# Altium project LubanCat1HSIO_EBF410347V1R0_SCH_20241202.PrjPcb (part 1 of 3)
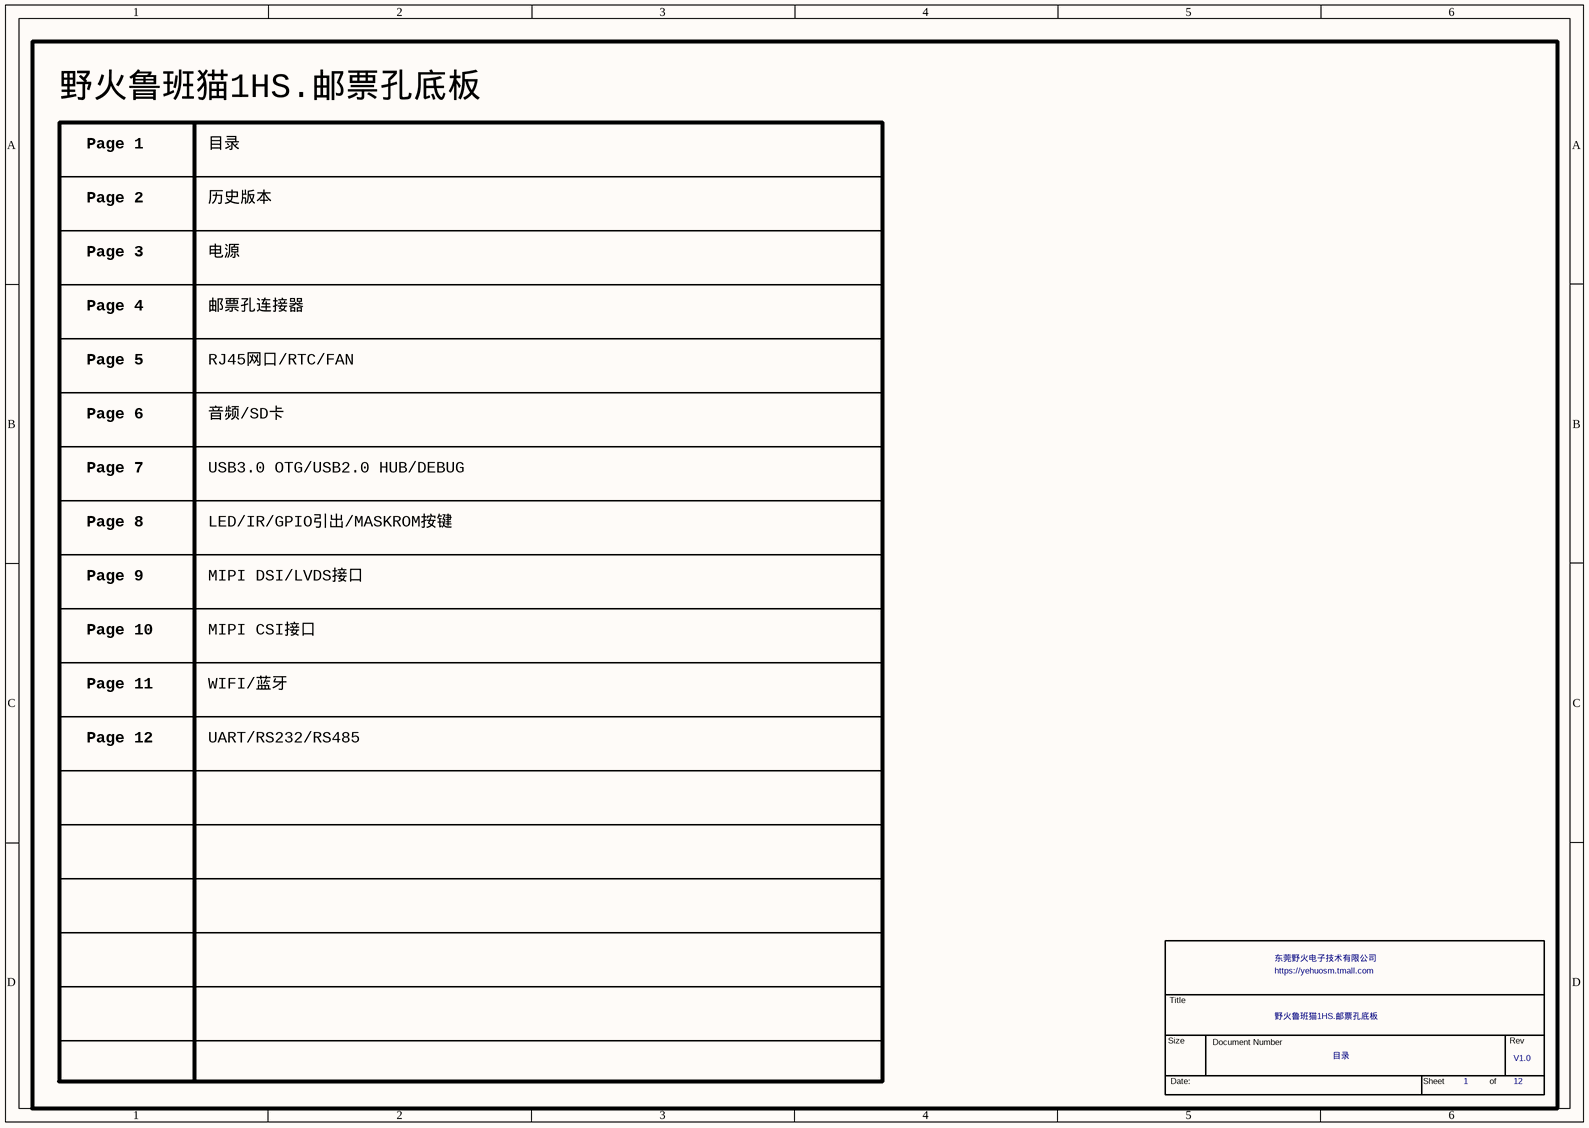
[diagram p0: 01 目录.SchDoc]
12 sheets, 578 parts. Net scope: global (net labels, ports and power ports of the same name join across sheets).
Sheets:
  01 目录.SchDoc
  02 历史版本.SchDoc
  03 电源.SchDoc
  04 邮票孔连接器.SchDoc
  05 RJ45网口_RTC_FAN.SchDoc
  06 音频_SD卡.SchDoc
  07 USB3.SchDoc
  08 LED_IR_GPIO引出_MASKRO.SchDoc
  09 MIPI DSI_LVDS接口.SchDoc
  10 MIPI CSI接口.SchDoc
  11 WIFI_蓝牙.SchDoc
  12 UART_RS232_RS485.SchDoc

## Sheet 01 目录.SchDoc
size 297 x 209 mm

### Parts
(Parts that share a designator on the sheet are numbered #1, #2 ... from top to bottom, then left to right.)
*#1  Page Count: 12  Page Number: 1  OrgName: 东莞野火电子技术有限公司  Title: 野火鲁班猫1HS.邮票孔底板  RevCode: V1.0  Doc: 目录  (hidden comment: TitleBlock_YHSCH)  (graphical)

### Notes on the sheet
- 野火鲁班猫1HS.邮票孔底板
- Page 1
- Page 2
- 目录
- 历史版本
- Page 3
- 电源
- Page 4
- 邮票孔连接器
- Page 5
- RJ45网口/RTC/FAN
- Page 6
- Page 7
- 音频/SD卡
- USB3.0 OTG/USB2.0 HUB/DEBUG
- Page 8
- LED/IR/GPIO引出/MASKROM按键
- Page 9
- MIPI DSI/LVDS接口
- Page 10
- MIPI CSI接口
- Page 11
- Page 12
- UART/RS232/RS485
- WIFI/蓝牙

## Sheet 02 历史版本.SchDoc
size 297 x 209 mm
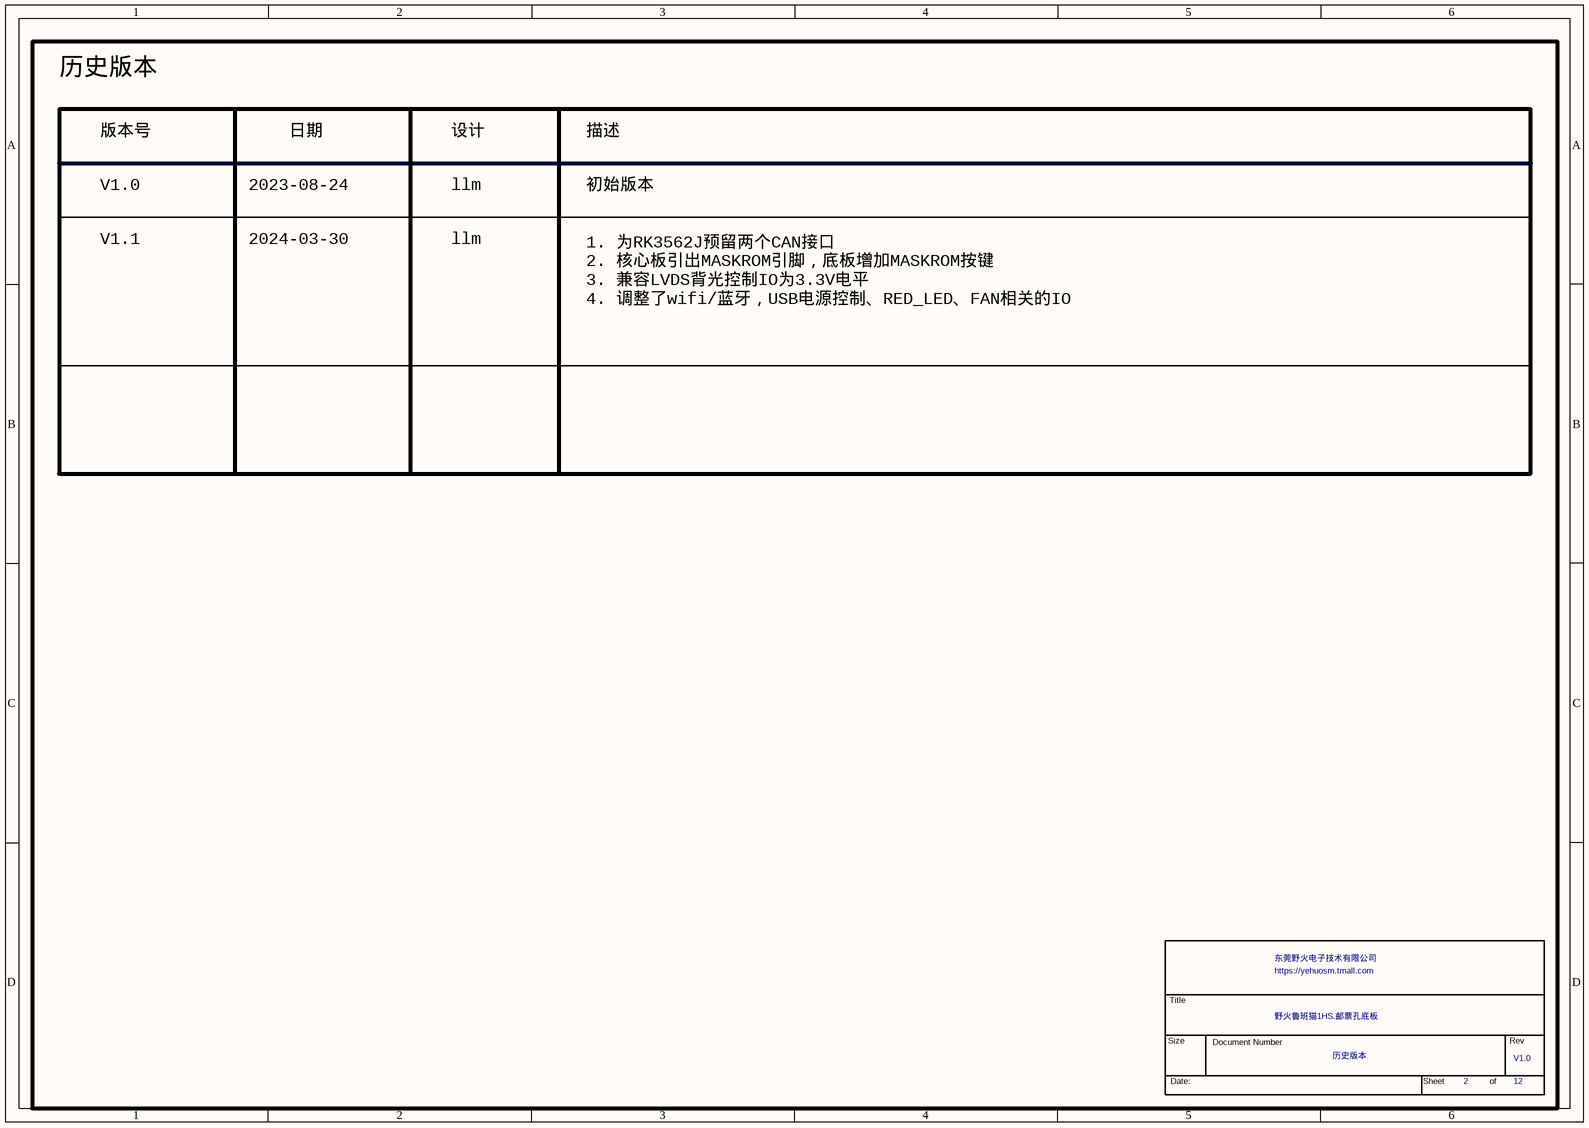
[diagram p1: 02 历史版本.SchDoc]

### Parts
(Parts that share a designator on the sheet are numbered #1, #2 ... from top to bottom, then left to right.)
*#2  Page Count: 12  Page Number: 2  OrgName: 东莞野火电子技术有限公司  Title: 野火鲁班猫1HS.邮票孔底板  RevCode: V1.0  Doc: 历史版本  (hidden comment: TitleBlock_YHSCH)  (graphical)

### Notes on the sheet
- 历史版本
- 版本号
- 日期
- 设计
- 描述
- V1.0
- 2023-08-24
- llm
- 初始版本
- V1.1
- 2024-03-30
- 1. 为RK3562J预留两个CAN接口
  2. 核心板引出MASKROM引脚，底板增加MASKROM按键
  3. 兼容LVDS背光控制IO为3.3V电平
  4. 调整了wifi/蓝牙，USB电源控制、RED_LED、FAN相关的IO

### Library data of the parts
*#2 = TitleBlock_YHSCH: Cage Code: 1

## Sheet 03 电源.SchDoc
size 297 x 209 mm
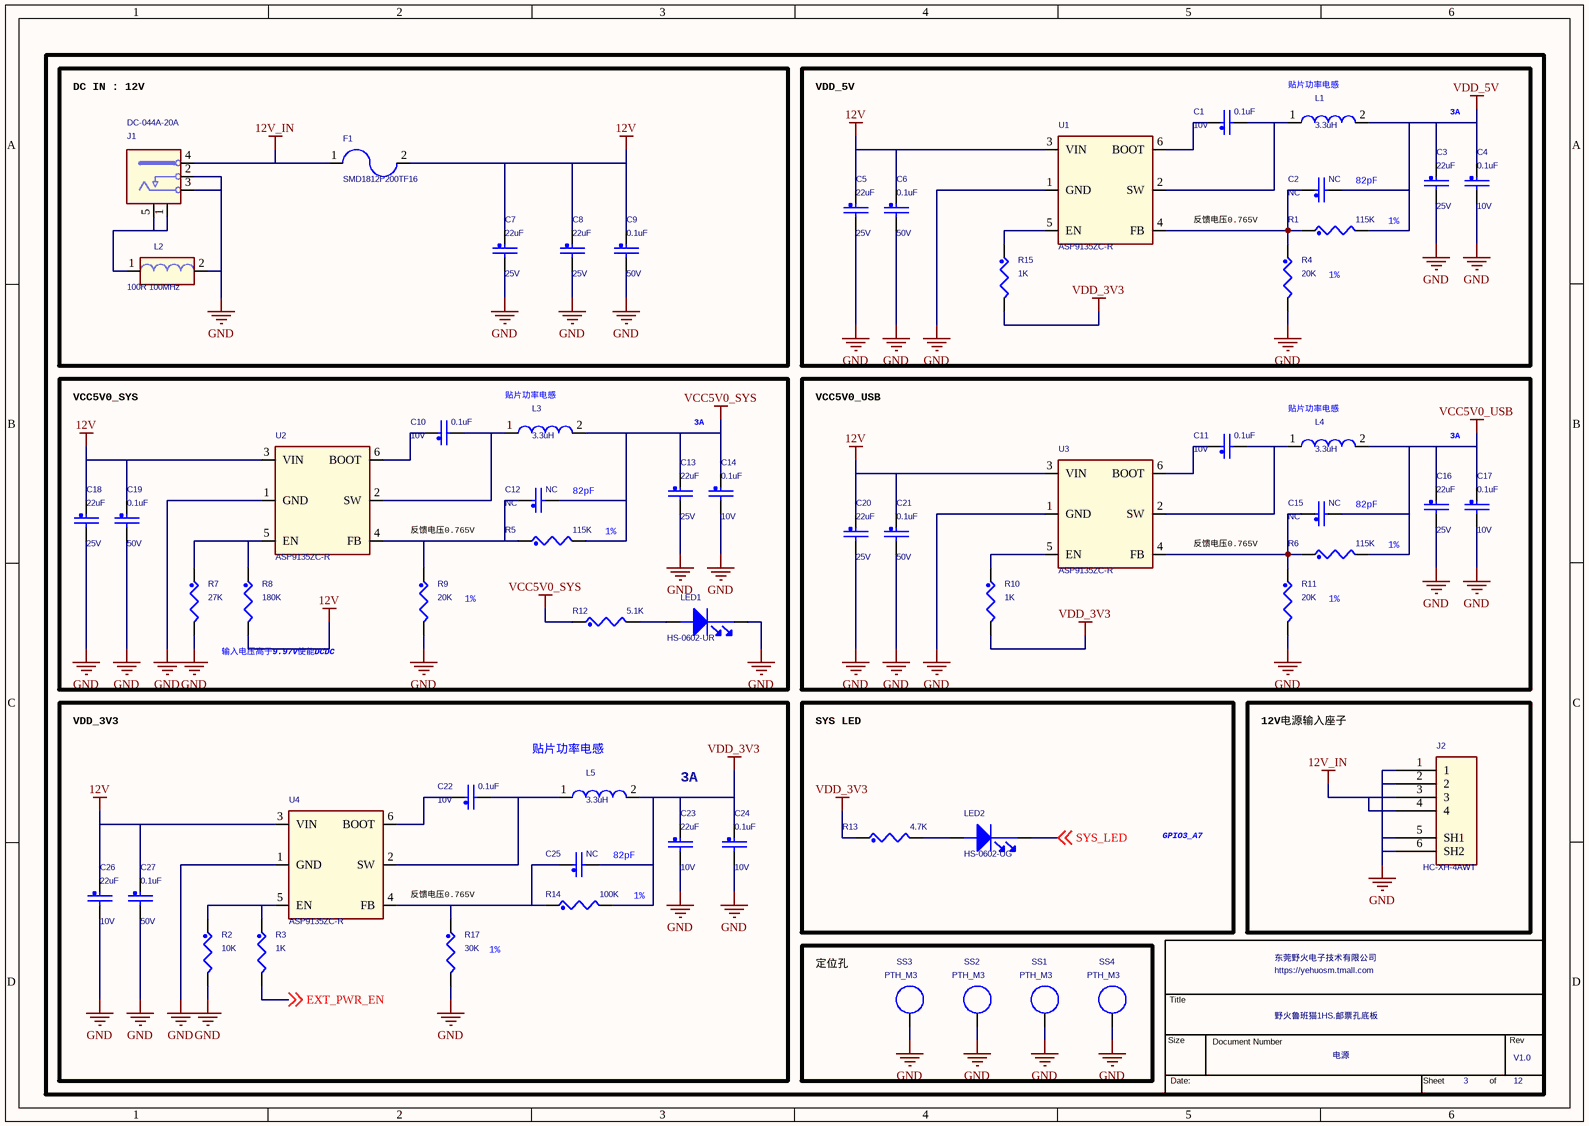
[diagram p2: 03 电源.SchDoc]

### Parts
(Parts that share a designator on the sheet are numbered #1, #2 ... from top to bottom, then left to right.)
*#3  Page Count: 12  Page Number: 3  OrgName: 东莞野火电子技术有限公司  Title: 野火鲁班猫1HS.邮票孔底板  RevCode: V1.0  Doc: 电源  (hidden comment: TitleBlock_YHSCH)  (graphical)
C1  0.1uF  Voltage: 10V  [C0402]
C2  NC  [C0402]
C3  22uF  Voltage: 25V  [C0805]
C4  0.1uF  Voltage: 10V  [C0402]
C5  22uF  Voltage: 25V  [C0805]
C6  0.1uF  Voltage: 50V  [C0402]
C7  22uF  Voltage: 25V  [C0805]
C8  22uF  Voltage: 25V  [C0805]
C9  0.1uF  Voltage: 50V  [C0402]
C10  0.1uF  Voltage: 10V  [C0402]
C11  0.1uF  Voltage: 10V  [C0402]
C12  NC  [C0402]
C13  22uF  Voltage: 25V  [C0805]
C14  0.1uF  Voltage: 10V  [C0402]
C15  NC  [C0402]
C16  22uF  Voltage: 25V  [C0805]
C17  0.1uF  Voltage: 10V  [C0402]
C18  22uF  Voltage: 25V  [C0805]
C19  0.1uF  Voltage: 50V  [C0402]
C20  22uF  Voltage: 25V  [C0805]
C21  0.1uF  Voltage: 50V  [C0402]
C22  0.1uF  Voltage: 10V  [C0402]
C23  22uF  Voltage: 10V  [C0603]
C24  0.1uF  Voltage: 10V  [C0402]
C25  NC  [C0402]
C26  22uF  Voltage: 10V  [C0603]
C27  0.1uF  Voltage: 50V  [C0402]
F1  SMD1812P200TF16  [F1812]
J1  DC-044A-20A  [dc_in_th_3p_10r1x11r6]
J2  HC-XH-4AWT  [HC-XH-4AWT]
L1  3.3uH  [l4520]
L2  100R 100MHz  [L0603]
L3  3.3uH  [l4520]
L4  3.3uH  [l4520]
L5  3.3uH  [l4520]
LED1  HS-0602-UR  [led_hs_0602_ur]
LED2  HS-0602-UG  [led_hs_0602_ur]
R1  115K  [R0402]
R2  10K  [R0402]
R3  1K  [R0402]
R4  20K  [R0402]
R5  115K  [R0402]
R6  115K  [R0402]
R7  27K  [R0402]
R8  180K  [R0402]
R9  20K  [R0402]
R10  1K  [R0402]
R11  20K  [R0402]
R12  5.1K  [R0402]
R13  4.7K  [R0402]
R14  100K  [R0402]
R15  1K  [R0402]
R17  30K  [R0402]
SS1  PTH_M3  [PTH_M3]
SS2  PTH_M3  [PTH_M3]
SS3  PTH_M3  [PTH_M3]
SS4  PTH_M3  [PTH_M3]
U1  ASP9135ZC-R  [SOT23_6]
U2  ASP9135ZC-R  [SOT23_6]
U3  ASP9135ZC-R  [SOT23_6]
U4  ASP9135ZC-R  [SOT23_6]

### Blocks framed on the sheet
DC IN : 12V: C7-C9 F1 J1 L2
VDD_5V: C1-C6 L1 R1 R4 R15 U1
VCC5V0_SYS: C10 C12-C14 C18 C19 L3 LED1 R5 R7-R9 R12 U2
VCC5V0_USB: C11 C15-C17 C20 C21 L4 R6 R10 R11 U3
3A: C22-C27 L5 R2 R3 R14 R17 U4
SYS LED: LED2 R13
12V电源输入座子: J2
定位孔: SS1-SS4

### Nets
12V: C5.1 C6.1 C7.1 C8.1 C9.1 C18.1 C19.1 C20.1 C21.1 C26.1 C27.1 F1.2 R8.2 U1.3(VIN) U2.3(VIN) U3.3(VIN) U4.3(VIN)
12V_IN: F1.1 J1.4 J2.3 J2.4
GND: C3.2 C4.2 C5.2 C6.2 C7.2 C8.2 C9.2 C13.2 C14.2 C16.2 C17.2 C18.2 C19.2 C20.2 C21.2 C23.2 C24.2 C26.2 C27.2 J1.2 J1.3 J2.1 J2.2 J2.5(SH1) J2.6(SH2) L2.2 LED1.1(CATHODE) R2.2 R4.2 R7.2 R9.2 R11.2 R17.2 SS1.1(NC_1) SS2.1(NC_1) SS3.1(NC_1) SS4.1(NC_1) U1.1(GND) U2.1(GND) U3.1(GND) U4.1(GND)
VCC5V0_SYS: C12.2 C13.1 C14.1 L3.2 R5.2 R12.1
VCC5V0_USB: C15.2 C16.1 C17.1 L4.2 R6.2
VDD_3V3: C23.1 C24.1 C25.2 L5.2 R10.2 R13.1 R14.2 R15.2
VDD_5V: C2.2 C3.1 C4.1 L1.2 R1.2
EXT_PWR_EN: R3.2 ; off-sheet EXT_PWR_EN
SYS_LED: LED2.1(CATHODE) ; off-sheet SYS_LED
NetC1_1: C1.1 U1.6(BOOT)
NetC1_2: C1.2 L1.1 U1.2(SW)
NetC2_1: C2.1 R1.1 R4.1 U1.4(FB)
NetC10_1: C10.1 U2.6(BOOT)
NetC10_2: C10.2 L3.1 U2.2(SW)
NetC11_1: C11.1 U3.6(BOOT)
NetC11_2: C11.2 L4.1 U3.2(SW)
NetC12_1: C12.1 R5.1 R9.1 U2.4(FB)
NetC15_1: C15.1 R6.1 R11.1 U3.4(FB)
NetC22_1: C22.1 U4.6(BOOT)
NetC22_2: C22.2 L5.1 U4.2(SW)
NetC25_1: C25.1 R14.1 R17.1 U4.4(FB)
NetJ1_1: J1.1 J1.5 L2.1
NetLED1_2: LED1.2(ANODE) R12.2
NetLED2_2: LED2.2(ANODE) R13.2
NetR2_1: R2.1 R3.1 U4.5(EN)
NetR7_1: R7.1 R8.1 U2.5(EN)
NetR10_1: R10.1 U3.5(EN)
NetR15_1: R15.1 U1.5(EN)

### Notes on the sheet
- (near L1) 贴片功率电感
- 3A
- 82pF
- 反馈电压0.765V
- 1%
- (near L3) 贴片功率电感
- (near L4) 贴片功率电感
- (near R5) 1%
- (near R9) 1%
- 输入电压高于9.97V使能DCDC
- VDD_3V3
- (near L5) 贴片功率电感
- (near C25) 82pF
- GPIO3_A7
- (near R17) 1%

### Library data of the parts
*#3 = TitleBlock_YHSCH: Cage Code: 1
C1 C4 C10 C11 C14 C17 C22 C24 = CAP_NP: CLASS: DISCRETE; 备注: H743挑战者; 生命周期: 量产; 价格: 0.003175; 规格书: 风华电容.pdf; 类别: 贴片电容0402; 品牌: 风华; 条码: EBFCIS230603155031; 规格编号: 0402B104K100NT; 规格: 贴片电容0.1uF 10% 10V X7R 0402
C2 C25 = CAP_NP: CLASS: DISCRETE; 规格: 贴片电容NC 预留; 条码: EBF29060149; 类别: 贴片电容0402
C3 C7 C8 C13 C18 C20 = CAP_NP: CLASS: DISCRETE; 规格: 贴片电容22uF 20% 25V X5R 0805; 规格编号: 0805X226M250NT; 条码: EBF29060173; 品牌: 风华; 类别: 贴片电容0805; 规格书: 风华电容.pdf; 价格: 0.285631; 生命周期: 量产
C5 C16 = CAP_NP: CLASS: DISCRETE; 生命周期: 量产; 价格: 0.285631; 规格书: 风华电容.pdf; 类别: 贴片电容0805; 品牌: 风华; 条码: EBF29060173; 规格编号: 0805X226M250NT; 规格: 贴片电容22uF 20% 25V X5R 0805
C6 C9 C27 = CAP_NP: CLASS: DISCRETE; 规格: 贴片电容0.1uF 10% 50V X5R 0402; 规格编号: 0402X104K500NT; 条码: EBF29060118; 品牌: 风华; 类别: 贴片电容0402; 规格书: 风华电容.pdf; 价格: 0.029826; 生命周期: 量产
C12 C15 = CAP_NP: CLASS: DISCRETE; 类别: 贴片电容0402; 条码: EBF29060149; 规格: 贴片电容NC 预留
C19 C21 = CAP_NP: CLASS: DISCRETE; 生命周期: 量产; 价格: 0.029826; 规格书: 风华电容.pdf; 类别: 贴片电容0402; 品牌: 风华; 条码: EBF29060118; 规格编号: 0402X104K500NT; 规格: 贴片电容0.1uF 10% 50V X5R 0402
C23 = CAP_NP: CLASS: DISCRETE; 生命周期: 量产; 价格: 0.078818; 规格书: 三星电容.pdf; 类别: 贴片电容0603; 品牌: 三星; 条码: EBF29060163; 规格编号: CL10A226MP8NUNE; 规格: 贴片电容22uF 20% 10V X5R 0603
C26 = CAP_NP: CLASS: DISCRETE; 规格: 贴片电容22uF 20% 10V X5R 0603; 规格编号: CL10A226MP8NUNE; 条码: EBF29060163; 品牌: 三星; 类别: 贴片电容0603; 规格书: 三星电容.pdf; 价格: 0.078818; 生命周期: 量产
F1 = FUSE: 生命周期: 量产; 价格: 0.385618; 规格书: 瑞隆源-自恢复保险丝.pdf; 类别: 自恢复保险丝; 品牌: 瑞隆源; 条码: EBF29270006; 规格: 自恢复保险丝 最大电压46V 最大电流100A 保持电流2A 跳闸电流4A
J1 = DC-044A-20A: 生命周期: 量产; 规格书: DC插座_内径_2MM外径_5.9MM.pdf; 类别: DC电源座; 条码: EBF29040093; 规格编号: DC-044A-20A DC; 规格: DC-044A-20A DC插座
J2 = 1X4PIN_SH: 规格: 间距：2.54mm 插针结构：1x4P 排数：1 每排PIN数：4 公母：公型插针 安装方式：卧贴 额定电流：3A 工作温度范围：-25℃~+85℃; 条码: EBFCIS230215084107; 品牌: 华灿天禄; 类别: XH连接器; 规格书: 华灿天禄_HC-XH-4AWT.pdf; 价格: 0.431422; 生命周期: 量产
L1 = IND: CLASS: DISCRETE; 价格: 1.5992; 规格编号: TMPC0402HP-3R3MG-Z02; 规格: 贴片电感3.3uH ±20% 3A 直流电阻69mΩ; 条码: EBF29050040; 品牌: 台庆; 类别: 贴片电感0402; 规格书: 台庆-功率电感.pdf; 生命周期: 量产
L2 = BEAD: CLASS: DISCRETE; 生命周期: 量产; 价格: 0.021567; 规格书: 顺络-磁珠.pdf; 类别: 贴片磁珠0603; 品牌: 顺络; 条码: EBF29050038; 规格编号: UPZ1608E101-3R0TF; 规格: 磁珠100Ω @100MHz 额定电流3A 直流电阻30mΩ
L3 L5 = IND: CLASS: DISCRETE; 价格: 1.5992; 规格编号: TMPC0402HP-3R3MG-Z02; 生命周期: 量产; 规格书: 台庆-功率电感.pdf; 类别: 贴片电感0402; 品牌: 台庆; 条码: EBF29050040; 规格: 贴片电感3.3uH ±20% 3A 直流电阻69mΩ
L4 = IND: CLASS: DISCRETE; 生命周期: 量产; 规格书: 台庆-功率电感.pdf; 类别: 贴片电感0402; 品牌: 台庆; 条码: EBF29050040; 规格: 贴片电感3.3uH ±20% 3A 直流电阻69mΩ; 规格编号: TMPC0402HP-3R3MG-Z02; 价格: 1.5992
LED1 = LED: 规格: 侧贴0602LED 红色; 条码: EBF29140054; 品牌: 鸿之森; 类别: 侧贴发光LED; 规格书: HS-0602-UR.pdf; 生命周期: 量产
LED2 = LED: 规格: 正向电压(VF)：3.2V 工作电流：5mA 功率：80mW 绿色; 条码: EBF29140060; 品牌: 鸿之森; 类别: 侧贴发光LED; 规格书: HS-0602-UG.pdf; 价格: 0.068705; 生命周期: 量产
R1 = RES: CLASS: DISCRETE; 生命周期: 量产; 价格: 0.006087; 规格书: YAGEO国巨厚膜无铅电阻.pdf; 类别: 贴片电阻0402; 品牌: 国巨; 条码: EBF29070290; 规格编号: AC0402FR-07115KL; 规格: 贴片电阻115K 1% 1/16W 0402
R2 = RES: CLASS: DISCRETE; 规格: 贴片电阻10K 1% 1/16W 0402; 规格编号: 0402WGF1002TCE; 条码: EBF29070046; 品牌: 厚声; 类别: 贴片电阻0402; 规格书: 厚声-无铅厚膜电阻.pdf; 价格: 0.002773; 生命周期: 量产
R3 = RES: CLASS: DISCRETE; 生命周期: 量产; 规格书: 合科泰-RI系列电阻.pdf; 类别: 贴片电阻0402; 品牌: 合科泰; 条码: EBF29070050; 规格编号: RI0402L1001FT; 规格: 贴片电阻1K 1% 1/16W 0402
R4 = RES: CLASS: DISCRETE; 生命周期: 量产; 价格: 0.002473; 规格书: 厚声-无铅厚膜电阻.pdf; 类别: 贴片电阻0402; 品牌: 厚声; 条码: EBF29070223; 规格编号: 0402WGF2002TCE; 规格: 贴片电阻20K 1% 1/16W 0402
R5 R6 = RES: CLASS: DISCRETE; 规格: 贴片电阻115K 1% 1/16W 0402; 规格编号: AC0402FR-07115KL; 条码: EBF29070290; 品牌: 国巨; 类别: 贴片电阻0402; 规格书: YAGEO国巨厚膜无铅电阻.pdf; 价格: 0.006087; 生命周期: 量产
R7 = RES: CLASS: DISCRETE; 生命周期: 量产; 价格: 0.007054; 规格书: YAGEO国巨厚膜无铅电阻.pdf; 类别: 贴片电阻0402; 品牌: 国巨; 条码: EBF29070003; 规格编号: AC0402FR-0727KL; 规格: 贴片电阻27K 1% 1/16W 0402
R8 = RES: CLASS: DISCRETE; 生命周期: 量产; 价格: 0.006152; 规格书: 厚声-无铅厚膜电阻.pdf; 类别: 贴片电阻0402; 品牌: 厚声; 条码: EBF29070288; 规格编号: CQ02WGF1803TCE; 规格: 贴片电阻180K 1% 1/16W 0402
R9 R11 = RES: CLASS: DISCRETE; 规格: 贴片电阻20K 1% 1/16W 0402; 规格编号: 0402WGF2002TCE; 条码: EBF29070223; 品牌: 厚声; 类别: 贴片电阻0402; 规格书: 厚声-无铅厚膜电阻.pdf; 价格: 0.002473; 生命周期: 量产
R10 R15 = RES: CLASS: DISCRETE; 规格: 贴片电阻1K 1% 1/16W 0402; 规格编号: RI0402L1001FT; 条码: EBF29070050; 品牌: 合科泰; 类别: 贴片电阻0402; 规格书: 合科泰-RI系列电阻.pdf; 生命周期: 量产
R12 = RES: CLASS: DISCRETE; 生命周期: 量产; 类别: 贴片电阻0402; 品牌: VO; 条码: EBF29070258; 规格编号: 0402F5101BV1906130014; 规格: 贴片电阻5.1K 1% 1/16W 0402
R13 = RES: CLASS: DISCRETE; 规格: 贴片电阻4.7K 1% 1/16W 0402; 规格编号: RI0402L4701FT; 条码: EBF29070047; 品牌: 合科泰; 类别: 贴片电阻0402; 规格书: 合科泰-RI系列电阻.pdf; 生命周期: 量产
R14 = RES: CLASS: DISCRETE; 规格: 贴片电阻100K 1% 1/16W 0402; 规格编号: RI0402L1003FT; 条码: EBF29070054; 品牌: 合科泰; 类别: 贴片电阻0402; 规格书: 合科泰-RI系列电阻.pdf; 生命周期: 量产
R17 = RES: CLASS: DISCRETE; 规格: 贴片电阻30K 1% 1/16W 0402; 规格编号: RI0402L3002FT; 条码: EBF29070048; 品牌: 合科泰; 类别: 贴片电阻0402; 规格书: 合科泰-RI系列电阻.pdf; 生命周期: 量产
SS1-SS4 = SPACER: CLASS: IC; 生命周期: 量产; 类别: M3螺丝孔; 品牌: 野火; 条码: EBFCIS220926100224; 规格编号: M3螺丝孔_有铜
U1-U4 = TP6327GS6: 备注: RK3566金手指与BTB底板替换物料; 生命周期: 量产; 规格书: 安森德_ASP9135ZC-R.pdf; 类别: 电源管理-DCDC; 品牌: 安森德; 条码: EBFCIS240710113940; 规格: DC-DC电源芯片 可输出电流 3A 开关工作频率 600kHz 输出类型 ADJ 输入电压范围：4V-18V

## Sheet 04 邮票孔连接器.SchDoc
size 297 x 209 mm
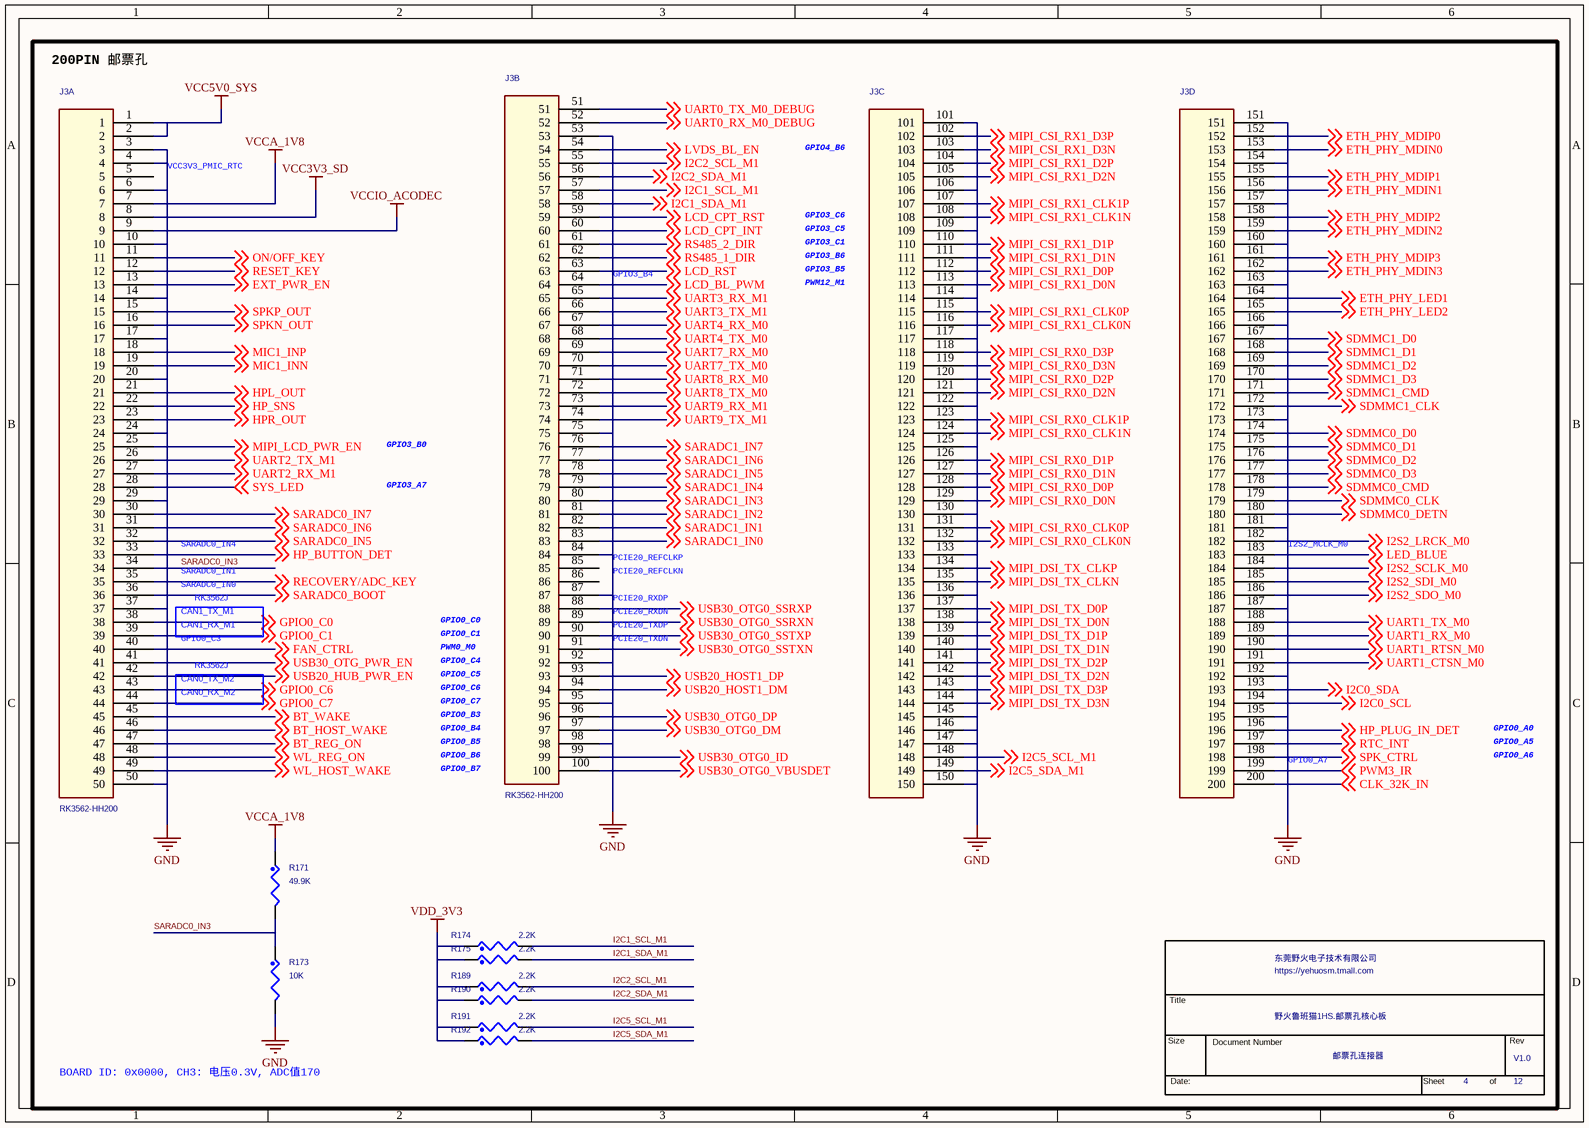
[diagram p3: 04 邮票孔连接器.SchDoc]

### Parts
(Parts that share a designator on the sheet are numbered #1, #2 ... from top to bottom, then left to right.)
*#4  Page Count: 12  Page Number: 4  OrgName: 东莞野火电子技术有限公司  Title: 野火鲁班猫1HS.邮票孔核心板  RevCode: V1.0  Doc: 邮票孔连接器  (hidden comment: TitleBlock_YHSCH)  (graphical)
J3  RK3562-HH200  [HH200-0R90-48R1X48R1-B]  (parts A,B,C,D of 4)
R171  49.9K  [R0402]
R173  10K  [R0402]
R174  2.2K  [R0402]
R175  2.2K  [R0402]
R189  2.2K  [R0402]
R190  2.2K  [R0402]
R191  2.2K  [R0402]
R192  2.2K  [R0402]

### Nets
GND: J3.3 J3.4 J3.6 J3.10 J3.14 J3.17 J3.20 J3.24 J3.29 J3.37 J3.50 J3.53 J3.75 J3.84 J3.87 J3.92 J3.95 J3.98 J3.101 J3.106 J3.109 J3.114 J3.117 J3.122 J3.125 J3.130 J3.133 J3.136 J3.145 J3.146 J3.147 J3.150 J3.151 J3.154 J3.157 J3.160 J3.163 J3.166 J3.173 J3.181 J3.187 J3.192 J3.195 R173.2
VCC3V3_SD: J3.8
VCC5V0_SYS: J3.1 J3.2
VCCA_1V8: J3.7 R171.1
VCCIO_ACODEC: J3.9
VDD_3V3: R174.1 R175.1 R189.1 R190.1 R191.1 R192.1
BT_HOST_WAKE: J3.46 ; off-sheet BT_HOST_WAKE
BT_REG_ON: J3.47 ; off-sheet BT_REG_ON
BT_WAKE: J3.45 ; off-sheet BT_WAKE
CLK_32K_IN: J3.200 ; off-sheet CLK_32K_IN
ETH_PHY_LED1: J3.164 ; off-sheet ETH_PHY_LED1
ETH_PHY_LED2: J3.165 ; off-sheet ETH_PHY_LED2
ETH_PHY_MDIN0: J3.153 ; off-sheet ETH_PHY_MDIN0
ETH_PHY_MDIN1: J3.156 ; off-sheet ETH_PHY_MDIN1
ETH_PHY_MDIN2: J3.159 ; off-sheet ETH_PHY_MDIN2
ETH_PHY_MDIN3: J3.162 ; off-sheet ETH_PHY_MDIN3
ETH_PHY_MDIP0: J3.152 ; off-sheet ETH_PHY_MDIP0
ETH_PHY_MDIP1: J3.155 ; off-sheet ETH_PHY_MDIP1
ETH_PHY_MDIP2: J3.158 ; off-sheet ETH_PHY_MDIP2
ETH_PHY_MDIP3: J3.161 ; off-sheet ETH_PHY_MDIP3
EXT_PWR_EN: J3.13 ; off-sheet EXT_PWR_EN
FAN_CTRL: J3.40 ; off-sheet FAN_CTRL
GPIO0_C0: J3.38 ; off-sheet GPIO0_C0
GPIO0_C1: J3.39 ; off-sheet GPIO0_C1
GPIO0_C6: J3.43 ; off-sheet GPIO0_C6
GPIO0_C7: J3.44 ; off-sheet GPIO0_C7
HP_BUTTON_DET: J3.33 ; off-sheet HP_BUTTON_DET
HP_PLUG_IN_DET: J3.196 ; off-sheet HP_PLUG_IN_DET
HP_SNS: J3.22 ; off-sheet HP_SNS
HPL_OUT: J3.21 ; off-sheet HPL_OUT
HPR_OUT: J3.23 ; off-sheet HPR_OUT
I2C0_SCL: J3.194 ; off-sheet I2C0_SCL
I2C0_SDA: J3.193 ; off-sheet I2C0_SDA
I2C1_SCL_M1: J3.57 R174.2 ; off-sheet I2C1_SCL_M1
I2C1_SDA_M1: J3.58 R175.2 ; off-sheet I2C1_SDA_M1
I2C2_SCL_M1: J3.55 R189.2 ; off-sheet I2C2_SCL_M1
I2C2_SDA_M1: J3.56 R190.2 ; off-sheet I2C2_SDA_M1
I2C5_SCL_M1: J3.148 R191.2 ; off-sheet I2C5_SCL_M1
I2C5_SDA_M1: J3.149 R192.2 ; off-sheet I2C5_SDA_M1
I2S2_LRCK_M0: J3.182 ; off-sheet I2S2_LRCK_M0
I2S2_SCLK_M0: J3.184 ; off-sheet I2S2_SCLK_M0
I2S2_SDI_M0: J3.185 ; off-sheet I2S2_SDI_M0
I2S2_SDO_M0: J3.186 ; off-sheet I2S2_SDO_M0
LCD_BL_PWM: J3.64 ; off-sheet LCD_BL_PWM
LCD_CPT_INT: J3.60 ; off-sheet LCD_CPT_INT
LCD_CPT_RST: J3.59 ; off-sheet LCD_CPT_RST
LCD_RST: J3.63 ; off-sheet LCD_RST
LED_BLUE: J3.183 ; off-sheet LED_BLUE
LVDS_BL_EN: J3.54 ; off-sheet LVDS_BL_EN
MIC1_INN: J3.19 ; off-sheet MIC1_INN
MIC1_INP: J3.18 ; off-sheet MIC1_INP
MIPI_CSI_RX0_CLK0N: J3.132 ; off-sheet MIPI_CSI_RX0_CLK0N
MIPI_CSI_RX0_CLK0P: J3.131 ; off-sheet MIPI_CSI_RX0_CLK0P
MIPI_CSI_RX0_CLK1N: J3.124 ; off-sheet MIPI_CSI_RX0_CLK1N
MIPI_CSI_RX0_CLK1P: J3.123 ; off-sheet MIPI_CSI_RX0_CLK1P
MIPI_CSI_RX0_D0N: J3.129 ; off-sheet MIPI_CSI_RX0_D0N
MIPI_CSI_RX0_D0P: J3.128 ; off-sheet MIPI_CSI_RX0_D0P
MIPI_CSI_RX0_D1N: J3.127 ; off-sheet MIPI_CSI_RX0_D1N
MIPI_CSI_RX0_D1P: J3.126 ; off-sheet MIPI_CSI_RX0_D1P
MIPI_CSI_RX0_D2N: J3.121 ; off-sheet MIPI_CSI_RX0_D2N
MIPI_CSI_RX0_D2P: J3.120 ; off-sheet MIPI_CSI_RX0_D2P
MIPI_CSI_RX0_D3N: J3.119 ; off-sheet MIPI_CSI_RX0_D3N
MIPI_CSI_RX0_D3P: J3.118 ; off-sheet MIPI_CSI_RX0_D3P
MIPI_CSI_RX1_CLK0N: J3.116 ; off-sheet MIPI_CSI_RX1_CLK0N
MIPI_CSI_RX1_CLK0P: J3.115 ; off-sheet MIPI_CSI_RX1_CLK0P
MIPI_CSI_RX1_CLK1N: J3.108 ; off-sheet MIPI_CSI_RX1_CLK1N
MIPI_CSI_RX1_CLK1P: J3.107 ; off-sheet MIPI_CSI_RX1_CLK1P
MIPI_CSI_RX1_D0N: J3.113 ; off-sheet MIPI_CSI_RX1_D0N
MIPI_CSI_RX1_D0P: J3.112 ; off-sheet MIPI_CSI_RX1_D0P
MIPI_CSI_RX1_D1N: J3.111 ; off-sheet MIPI_CSI_RX1_D1N
MIPI_CSI_RX1_D1P: J3.110 ; off-sheet MIPI_CSI_RX1_D1P
MIPI_CSI_RX1_D2N: J3.105 ; off-sheet MIPI_CSI_RX1_D2N
MIPI_CSI_RX1_D2P: J3.104 ; off-sheet MIPI_CSI_RX1_D2P
MIPI_CSI_RX1_D3N: J3.103 ; off-sheet MIPI_CSI_RX1_D3N
MIPI_CSI_RX1_D3P: J3.102 ; off-sheet MIPI_CSI_RX1_D3P
MIPI_DSI_TX_CLKN: J3.135 ; off-sheet MIPI_DSI_TX_CLKN
MIPI_DSI_TX_CLKP: J3.134 ; off-sheet MIPI_DSI_TX_CLKP
MIPI_DSI_TX_D0N: J3.138 ; off-sheet MIPI_DSI_TX_D0N
MIPI_DSI_TX_D0P: J3.137 ; off-sheet MIPI_DSI_TX_D0P
MIPI_DSI_TX_D1N: J3.140 ; off-sheet MIPI_DSI_TX_D1N
MIPI_DSI_TX_D1P: J3.139 ; off-sheet MIPI_DSI_TX_D1P
MIPI_DSI_TX_D2N: J3.142 ; off-sheet MIPI_DSI_TX_D2N
MIPI_DSI_TX_D2P: J3.141 ; off-sheet MIPI_DSI_TX_D2P
MIPI_DSI_TX_D3N: J3.144 ; off-sheet MIPI_DSI_TX_D3N
MIPI_DSI_TX_D3P: J3.143 ; off-sheet MIPI_DSI_TX_D3P
MIPI_LCD_PWR_EN: J3.25 ; off-sheet MIPI_LCD_PWR_EN
ON/OFF_KEY: J3.11 ; off-sheet ON/OFF_KEY
PWM3_IR: J3.199 ; off-sheet PWM3_IR
RECOVERY/ADC_KEY: J3.35 ; off-sheet RECOVERY/ADC_KEY
RESET_KEY: J3.12 ; off-sheet RESET_KEY
RS485_1_DIR: J3.62 ; off-sheet RS485_1_DIR
RS485_2_DIR: J3.61 ; off-sheet RS485_2_DIR
RTC_INT: J3.197 ; off-sheet RTC_INT
SARADC0_BOOT: J3.36 ; off-sheet SARADC0_BOOT
SARADC0_IN3: J3.34 R171.2 R173.1
SARADC0_IN5: J3.32 ; off-sheet SARADC0_IN5
SARADC0_IN6: J3.31 ; off-sheet SARADC0_IN6
SARADC0_IN7: J3.30 ; off-sheet SARADC0_IN7
SARADC1_IN0: J3.83 ; off-sheet SARADC1_IN0
SARADC1_IN1: J3.82 ; off-sheet SARADC1_IN1
SARADC1_IN2: J3.81 ; off-sheet SARADC1_IN2
SARADC1_IN3: J3.80 ; off-sheet SARADC1_IN3
SARADC1_IN4: J3.79 ; off-sheet SARADC1_IN4
SARADC1_IN5: J3.78 ; off-sheet SARADC1_IN5
SARADC1_IN6: J3.77 ; off-sheet SARADC1_IN6
SARADC1_IN7: J3.76 ; off-sheet SARADC1_IN7
SDMMC0_CLK: J3.179 ; off-sheet SDMMC0_CLK
SDMMC0_CMD: J3.178 ; off-sheet SDMMC0_CMD
SDMMC0_D0: J3.174 ; off-sheet SDMMC0_D0
SDMMC0_D1: J3.175 ; off-sheet SDMMC0_D1
SDMMC0_D2: J3.176 ; off-sheet SDMMC0_D2
SDMMC0_D3: J3.177 ; off-sheet SDMMC0_D3
SDMMC0_DETN: J3.180 ; off-sheet SDMMC0_DETN
SDMMC1_CLK: J3.172 ; off-sheet SDMMC1_CLK
SDMMC1_CMD: J3.171 ; off-sheet SDMMC1_CMD
SDMMC1_D0: J3.167 ; off-sheet SDMMC1_D0
SDMMC1_D1: J3.168 ; off-sheet SDMMC1_D1
SDMMC1_D2: J3.169 ; off-sheet SDMMC1_D2
SDMMC1_D3: J3.170 ; off-sheet SDMMC1_D3
SPK_CTRL: J3.198 ; off-sheet SPK_CTRL
SPKN_OUT: J3.16 ; off-sheet SPKN_OUT
SPKP_OUT: J3.15 ; off-sheet SPKP_OUT
SYS_LED: J3.28 ; off-sheet SYS_LED
UART0_RX_M0_DEBUG: J3.52 ; off-sheet UART0_RX_M0_DEBUG
UART0_TX_M0_DEBUG: J3.51 ; off-sheet UART0_TX_M0_DEBUG
UART1_CTSN_M0: J3.191 ; off-sheet UART1_CTSN_M0
UART1_RTSN_M0: J3.190 ; off-sheet UART1_RTSN_M0
UART1_RX_M0: J3.189 ; off-sheet UART1_RX_M0
UART1_TX_M0: J3.188 ; off-sheet UART1_TX_M0
UART2_RX_M1: J3.27 ; off-sheet UART2_RX_M1
UART2_TX_M1: J3.26 ; off-sheet UART2_TX_M1
UART3_RX_M1: J3.65 ; off-sheet UART3_RX_M1
UART3_TX_M1: J3.66 ; off-sheet UART3_TX_M1
UART4_RX_M0: J3.67 ; off-sheet UART4_RX_M0
UART4_TX_M0: J3.68 ; off-sheet UART4_TX_M0
UART7_RX_M0: J3.69 ; off-sheet UART7_RX_M0
UART7_TX_M0: J3.70 ; off-sheet UART7_TX_M0
UART8_RX_M0: J3.71 ; off-sheet UART8_RX_M0
UART8_TX_M0: J3.72 ; off-sheet UART8_TX_M0
UART9_RX_M1: J3.73 ; off-sheet UART9_RX_M1
UART9_TX_M1: J3.74 ; off-sheet UART9_TX_M1
USB20_HOST1_DM: J3.94 ; off-sheet USB20_HOST1_DM
USB20_HOST1_DP: J3.93 ; off-sheet USB20_HOST1_DP
USB20_HUB_PWR_EN: J3.42 ; off-sheet USB20_HUB_PWR_EN
USB30_OTG0_DM: J3.97 ; off-sheet USB30_OTG0_DM
USB30_OTG0_DP: J3.96 ; off-sheet USB30_OTG0_DP
USB30_OTG0_ID: J3.99 ; off-sheet USB30_OTG0_ID
USB30_OTG0_SSRXN: J3.89 ; off-sheet USB30_OTG0_SSRXN
USB30_OTG0_SSRXP: J3.88 ; off-sheet USB30_OTG0_SSRXP
USB30_OTG0_SSTXN: J3.91 ; off-sheet USB30_OTG0_SSTXN
USB30_OTG0_SSTXP: J3.90 ; off-sheet USB30_OTG0_SSTXP
USB30_OTG0_VBUSDET: J3.100 ; off-sheet USB30_OTG0_VBUSDET
USB30_OTG_PWR_EN: J3.41 ; off-sheet USB30_OTG_PWR_EN
WL_HOST_WAKE: J3.49 ; off-sheet WL_HOST_WAKE
WL_REG_ON: J3.48 ; off-sheet WL_REG_ON

Not connected (* = marked no-connect by the designer): J3 5 85 86

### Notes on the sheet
- 200PIN 邮票孔
- VCC3V3_PMIC_RTC
- GPIO4_B6
- GPIO3_C6
- GPIO3_C5
- GPIO3_C1
- GPIO3_B6
- GPIO3_B5
- GPIO3_B4
- PWM12_M1
- GPIO3_B0
- GPIO3_A7
- SARADC0_IN4
- SARADC0_IN1
- SARADC0_IN0
- RK3562J
- PCIE20_REFCLKP
- PCIE20_REFCLKN
- PCIE20_RXDP
- I2S2_MCLK_M0
- GPIO0_C3
- CAN1_RX_M1
- CAN1_TX_M1
- GPIO0_C0
- GPIO0_C1
- PWM0_M0
- GPIO0_C4
- GPIO0_C5
- PCIE20_RXDN
- PCIE20_TXDP
- PCIE20_TXDN
- CAN0_TX_M2
- CAN0_RX_M2
- GPIO0_C6
- GPIO0_C7
- GPIO0_B3
- GPIO0_B4
- GPIO0_B5
- GPIO0_A0
- GPIO0_A5
- GPIO0_B6
- GPIO0_B7
- GPIO0_A7
- GPIO0_A6
- BOARD ID: 0x0000, CH3: 电压0.3V, ADC值170

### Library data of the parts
*#4 = TitleBlock_YHSCH: Cage Code: 1
J3 = RK3562-HH200: 规格: RK3562邮票孔核心板 引脚数量200P 引脚间距0.9mm 尺寸48.1x48.1mm; 条码: EBFCIS240902134638; 品牌: 野火; 类别: 邮票孔核心板; 生命周期: 量产; 备注: 鲁班猫1HS
R171 = RES: CLASS: DISCRETE; 规格: 贴片电阻49.9K 1% 1/16W 0402; 规格编号: RMC040249.9K1%N; 条码: EBF29070257; 品牌: 幸亚; 类别: 贴片电阻0402; 规格书: 幸亚电阻.pdf; 价格: 0.015936; 生命周期: 量产
R173 = RES: as R2 on sheet 03 电源
R174 R189 R191 = RES: CLASS: DISCRETE; 规格: 贴片电阻2.2K 1% 1/16W 0402; 规格编号: RI0402L2201FT; 条码: EBF29070051; 品牌: 合科泰; 类别: 贴片电阻0402; 规格书: 合科泰-RI系列电阻.pdf; 生命周期: 量产
R175 R190 R192 = RES: CLASS: DISCRETE; 生命周期: 量产; 规格书: 合科泰-RI系列电阻.pdf; 类别: 贴片电阻0402; 品牌: 合科泰; 条码: EBF29070051; 规格编号: RI0402L2201FT; 规格: 贴片电阻2.2K 1% 1/16W 0402

## Sheet 05 RJ45网口_RTC_FAN.SchDoc
size 297 x 209 mm
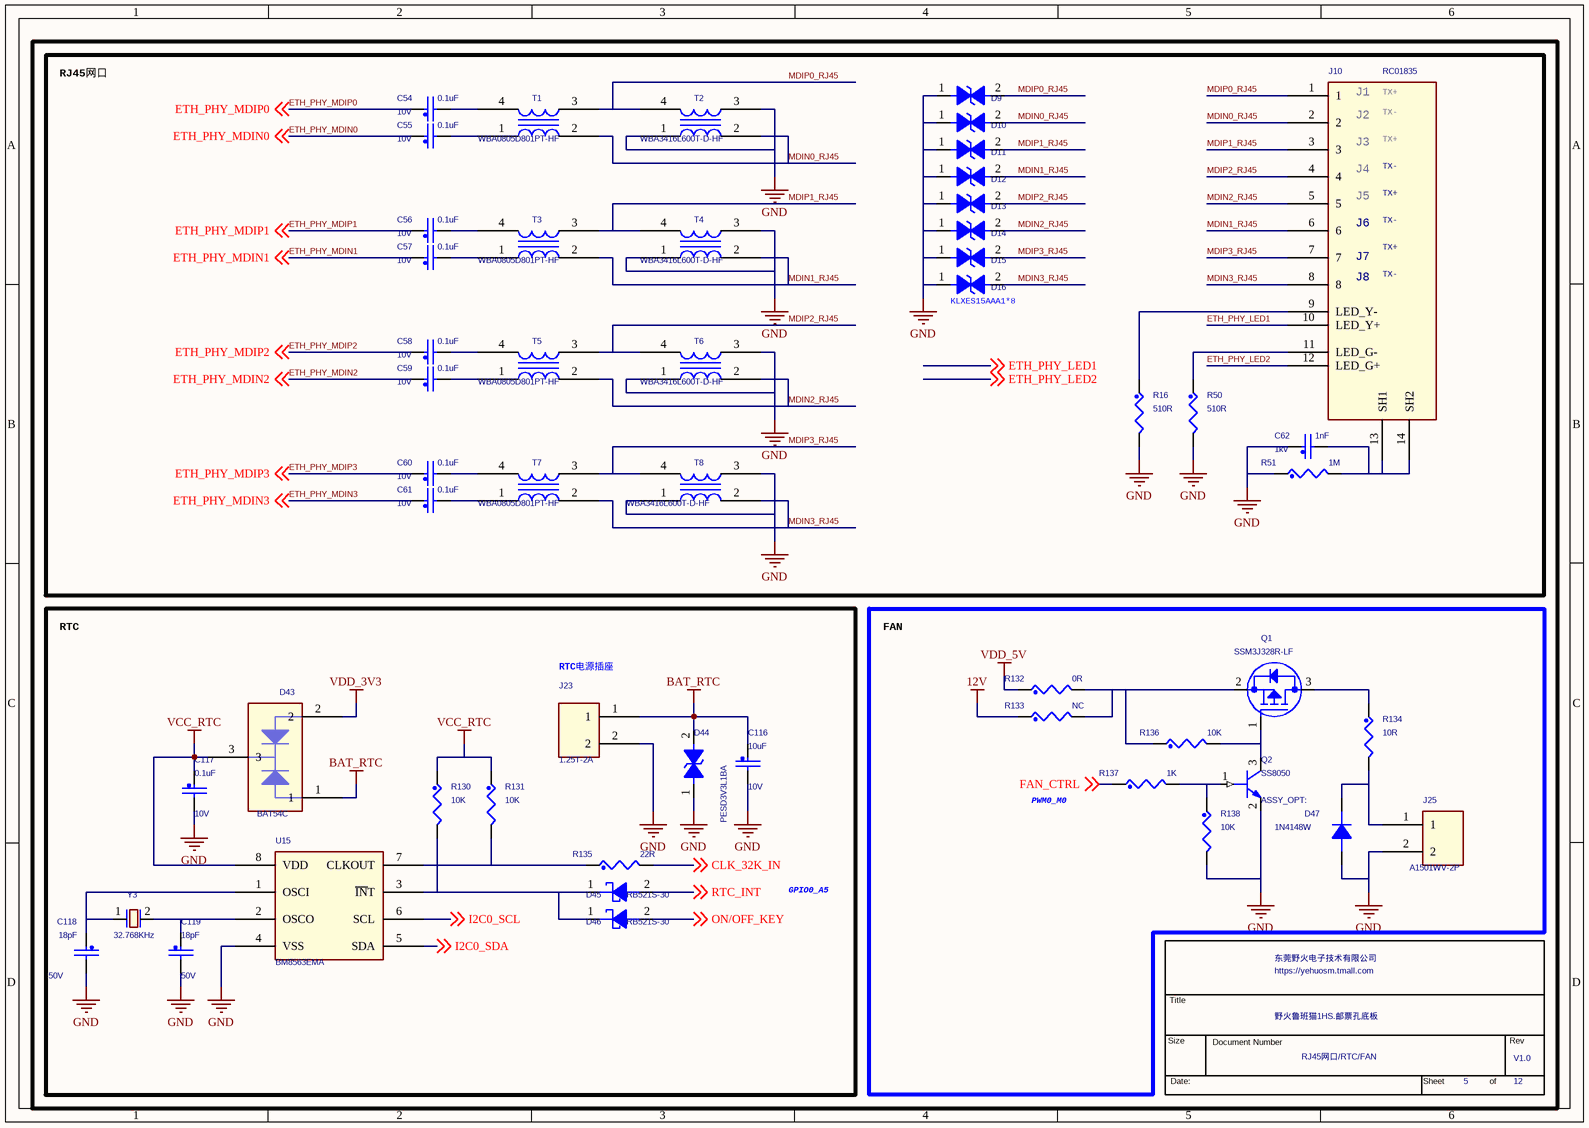
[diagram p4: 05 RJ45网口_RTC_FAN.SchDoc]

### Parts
(Parts that share a designator on the sheet are numbered #1, #2 ... from top to bottom, then left to right.)
*#5  Page Count: 12  Page Number: 5  OrgName: 东莞野火电子技术有限公司  Title: 野火鲁班猫1HS.邮票孔底板  RevCode: V1.0  Doc: RJ45网口/RTC/FAN  (hidden comment: TitleBlock_YHSCH)  (graphical)
C54  0.1uF  Voltage: 10V  [C0402]
C55  0.1uF  Voltage: 10V  [C0402]
C56  0.1uF  Voltage: 10V  [C0402]
C57  0.1uF  Voltage: 10V  [C0402]
C58  0.1uF  Voltage: 10V  [C0402]
C59  0.1uF  Voltage: 10V  [C0402]
C60  0.1uF  Voltage: 10V  [C0402]
C61  0.1uF  Voltage: 10V  [C0402]
C62  1nF  Voltage: 1kv  [C0805]
C116  10uF  Voltage: 10V  [C0402]
C117  0.1uF  Voltage: 10V  [C0402]
C118  18pF  Voltage: 50V  [C0402]
C119  18pF  Voltage: 50V  [C0402]
D9  KLXES15AAA1  [D0603/SMD]  (value not drawn)
D10  KLXES15AAA1  [D0603/SMD]  (value not drawn)
D11  KLXES15AAA1  [D0603/SMD]  (value not drawn)
D12  KLXES15AAA1  [D0603/SMD]  (value not drawn)
D13  KLXES15AAA1  [D0603/SMD]  (value not drawn)
D14  KLXES15AAA1  [D0603/SMD]  (value not drawn)
D15  KLXES15AAA1  [D0603/SMD]  (value not drawn)
D16  KLXES15AAA1  [D0603/SMD]  (value not drawn)
D43  BAT54C  [SOT23]
D44  PESD3V3L1BA  [D0603/SMD]
D45  RB521S-30  [SOD523]
D46  RB521S-30  [SOD523]
D47  1N4148W  [SOD-123]
J10  RC01835  [RJ8-15R2X16R2-TM-LED]
J23  1.25T-2A  [gh1p25_th_2p]
J25  A1501WV-2P  [zh1p5mm_th_2p]
Q1  SSM3J328R-LF  [SOT23]
Q2  SS8050  [SOT23]
R16  510R  [R0402]
R50  510R  [R0402]
R51  1M  [R0805]
R130  10K  [R0402]
R131  10K  [R0402]
R132  0R  [R0603]
R133  NC  [R0603]
R134  10R  [R0805]
R135  22R  [R0402]
R136  10K  [R0402]
R137  1K  [R0402]
R138  10K  [R0402]
T1  WBA0805D801PT-HF  [L4_2012_T]
T2  WBA3416L600T-D-HF  [L4_3216_T]
T3  WBA0805D801PT-HF  [L4_2012_T]
T4  WBA3416L600T-D-HF  [L4_3216_T]
T5  WBA0805D801PT-HF  [L4_2012_T]
T6  WBA3416L600T-D-HF  [L4_3216_T]
T7  WBA0805D801PT-HF  [L4_2012_T]
T8  WBA3416L600T-D-HF  [L4_3216_T]
U15  BM8563EMA  [msop-8]
Y3  32.768KHz  [3215]

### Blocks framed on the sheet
RJ45网口: C54-C62 D9-D16 J10 R16 R50 R51 T1-T8
RTC: C116-C119 D43-D46 J23 R130 R131 R135 U15 Y3
FAN: D47 J25 Q1 Q2 R132-R134 R136-R138

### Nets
12V: R133.1
BAT_RTC: C116.1 D43.1 D44.2 J23.1
GND: C62.1 C116.2 C117.2 C118.2 C119.2 D9.1 D10.1 D11.1 D12.1 D13.1 D14.1 D15.1 D16.1 D44.1 D47.2(A) J23.2 J25.2 Q2.2(EMITTER) R16.2 R50.2 R51.1 R138.2 T2.1 T2.3 T4.1 T4.3 T6.1 T6.3 T8.1 T8.3 U15.4(VSS)
VCC_RTC: C117.1 D43.3 R130.1 R131.1 U15.8(VDD)
VDD_3V3: D43.2
VDD_5V: R132.1
CLK_32K_IN: R135.2 ; off-sheet CLK_32K_IN
ETH_PHY_LED1: J10.10(LED_Y+) ; off-sheet ETH_PHY_LED1
ETH_PHY_LED2: J10.12(LED_G+) ; off-sheet ETH_PHY_LED2
ETH_PHY_MDIN0: C55.1 ; off-sheet ETH_PHY_MDIN0
ETH_PHY_MDIN1: C57.1 ; off-sheet ETH_PHY_MDIN1
ETH_PHY_MDIN2: C59.1 ; off-sheet ETH_PHY_MDIN2
ETH_PHY_MDIN3: C61.1 ; off-sheet ETH_PHY_MDIN3
ETH_PHY_MDIP0: C54.1 ; off-sheet ETH_PHY_MDIP0
ETH_PHY_MDIP1: C56.1 ; off-sheet ETH_PHY_MDIP1
ETH_PHY_MDIP2: C58.1 ; off-sheet ETH_PHY_MDIP2
ETH_PHY_MDIP3: C60.1 ; off-sheet ETH_PHY_MDIP3
FAN_CTRL: R137.1 ; off-sheet FAN_CTRL
I2C0_SCL: U15.6(SCL) ; off-sheet I2C0_SCL
I2C0_SDA: U15.5(SDA) ; off-sheet I2C0_SDA
MDIN0_RJ45: D10.2 J10.2 T1.2 T2.2
MDIN1_RJ45: D12.2 J10.6 T3.2 T4.2
MDIN2_RJ45: D14.2 J10.5 T5.2 T6.2
MDIN3_RJ45: D16.2 J10.8 T7.2 T8.2
MDIP0_RJ45: D9.2 J10.1 T1.3 T2.4
MDIP1_RJ45: D11.2 J10.3 T3.3 T4.4
MDIP2_RJ45: D13.2 J10.4 T5.3 T6.4
MDIP3_RJ45: D15.2 J10.7 T7.3 T8.4
ON/OFF_KEY: D46.2 ; off-sheet ON/OFF_KEY
RTC_INT: D45.2 ; off-sheet RTC_INT
NetC54_2: C54.2 T1.4
NetC55_2: C55.2 T1.1
NetC56_2: C56.2 T3.4
NetC57_2: C57.2 T3.1
NetC58_2: C58.2 T5.4
NetC59_2: C59.2 T5.1
NetC60_2: C60.2 T7.4
NetC61_2: C61.2 T7.1
NetC62_2: C62.2 J10.13(SH1) J10.14(SH2) R51.2
NetC118_1: C118.1 U15.1(OSCI) Y3.1
NetC119_1: C119.1 U15.2(OSCO) Y3.2
NetD45_1: D45.1 D46.1 R130.2 U15.3(~{IN}T)
NetD47_1: D47.1(K) J25.1 R134.2
NetJ10_9: J10.9(LED_Y-) R16.1
NetJ10_11: J10.11(LED_G-) R50.1
NetQ1_1: Q1.1(GATE) Q2.3(COLLECTOR) R136.2
NetQ1_2: Q1.2(SOURCE) R132.2 R133.2 R136.1
NetQ1_3: Q1.3(DRAIN) R134.1
NetQ2_1: Q2.1(BASE) R137.2 R138.1
NetR131_2: R131.2 R135.1 U15.7(CLKOUT)

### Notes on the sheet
- (near D16) KLXES15AAA1*8
- (near J23) RTC电源插座
- PWM0_M0
- GPIO0_A5

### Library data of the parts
*#5 = TitleBlock_YHSCH: Cage Code: 1
C54-C61 C117 = CAP_NP: CLASS: DISCRETE; 规格: 贴片电容0.1uF 10% 10V X7R 0402; 规格编号: 0402B104K100NT; 条码: EBFCIS230603155031; 品牌: 风华; 类别: 贴片电容0402; 规格书: 风华电容.pdf; 价格: 0.003175; 生命周期: 量产; 备注: H743挑战者
C62 = CAP_NP: CLASS: DISCRETE; 生命周期: 量产; 价格: 0.083527; 规格书: 华新科0805系列高压贴片电容.pdf; 类别: 贴片电容0805; 品牌: 华新科; 条码: EBF29060304; 规格编号: 0805B102K102CT; 规格: 贴片电容1nF 10% 1kV X7R 0805
C116 = CAP_NP: CLASS: DISCRETE; 规格: 贴片电容10uF 20% 10V X5R 0402; 规格编号: CL05A106MP8NUB8; 条码: EBF29060247; 品牌: 三星; 类别: 贴片电容0402; 规格书: 三星电容.pdf; 价格: 0.518415; 生命周期: 量产
C118 = CAP_NP: CLASS: DISCRETE; 规格: 贴片电容18pF 5% 50V C0G 0402; 规格编号: 0402CG180J500NT; 条码: EBF29060235; 品牌: 风华; 类别: 贴片电容0402; 规格书: 风华电容.pdf; 价格: 0.00515; 生命周期: 量产
C119 = CAP_NP: CLASS: DISCRETE; 生命周期: 量产; 价格: 0.00515; 规格书: 风华电容.pdf; 类别: 贴片电容0402; 品牌: 风华; 条码: EBF29060235; 规格编号: 0402CG180J500NT; 规格: 贴片电容18pF 5% 50V C0G 0402
D9-D16 = DIODE BI-DIR TRIG: 生命周期: 量产; 价格: 0.09719; 规格书: KLXES15AAA1.pdf; 类别: 贴片ESD; 品牌: 永裕泰; 条码: EBF29140063; 规格: 用于 USB3.0、HDMI 0.5pF、5V、±15kV ESD 保护二极管
D43 = BAT54C: 丝印: KL3; 生命周期: 量产; 价格: 0.077486; 规格书: 江苏长电_BAT54C.pdf; 类别: 贴片肖特基二极管; 品牌: 江苏长电; 条码: EBF29140062; 规格: 肖特基双二极管 直流反向耐压(Vr) 30V 平均整流电流(Io) 300mA 正向压降(Vf) 1V@100mA
D44 = DIODE BI-DIR TRIG: 丝印: AB; 生命周期: 量产; 价格: 0.31497; 规格书: 安世-PESD3V3L1BA-115.pdf; 类别: 贴片ESD; 品牌: 安世; 条码: EBF29140003; 规格编号: PESD3V3L1BA 115; 规格: 防静电保护ESD二极管 箝位电压26V 击穿电压5.8V 反向关断电压3.3V
D45 D46 = DIODE_SCHTKY: CLASS: IC; 规格: 直流反向耐压(Vr)：30V 平均整流电流(Io)：200mA 正向压降(Vf)：500mV@200mA 30V@100mA,VF=350mV@10mA; 条码: EBFCIS221114153437; 品牌: 江苏长电; 类别: 贴片肖特基二极管; 规格书: 江苏长电_RB521S-30.pdf; 价格: 0.06781; 生命周期: 量产
D47 = DIODE: 丝印: T4; 生命周期: 量产; 价格: 0.061637; 规格书: 1N4148WT4.pdf; 类别: 贴片开关二极管; 品牌: 江苏长电; 条码: EBF29140015; 规格: 开关二极管 反向耐压值100V 平均整流电流150mA 正向压降1.25V 150mA 功率500mW
J10 = RC01835: 生命周期: 量产; 价格: 2.41; 规格书: 瑞川_RC01835.PDF; 类别: 网口; 品牌: 瑞川; 条码: EBF29040107; 规格: RJ45 沉板 带灯 带屏蔽 12p RC01835
J23 = 1X2PIN: 规格: 间距=1.25mm 直插 2P针座连接器; 条码: EBF29040105; 品牌: 创都; 类别: 1.25连接器; 规格书: 1.25T-2A.pdf; 生命周期: 量产
J25 = 1X2PIN: 生命周期: 量产; 规格书: 长江连接器_A1501WV-2P.PDF; 类别: 线对板连接器; 品牌: 长江连接器; 条码: EBF29040095; 规格: ZH1.5直插 镀锡 2P 针座连接器
Q1 = MOSFET_P: CLASS: IC; 丝印: KFH-XXX; 生命周期: 量产; 价格: 0.447836; 规格书: SSM3J328R-LF.pdf; 类别: P-MOS; 品牌: 东芝; 条码: EBF29280008; 规格编号: SSM3J328R LF; 规格: P沟道MOS 导通电阻29.8mΩ 电流3A 1.5V可驱动
Q2 = NPN: CLASS: IC; 丝印: Y1; 生命周期: 量产; 价格: 0.086744; 规格书: 江苏长电-SS8050Y1.pdf; 类别: 贴片三极管SOT-23; 品牌: 江苏长电; 条码: EBF29090001; 规格: 贴片三极管SS8050 集电极电流1.5A 额定功率300mW NPN
R16 R50 = RES: CLASS: DISCRETE; 生命周期: 量产; 价格: 0.003791; 规格书: 厚声-无铅厚膜电阻.pdf; 类别: 贴片电阻0402; 品牌: 厚声; 条码: EBF29070293; 规格编号: 0402WGF5100TCE; 规格: 贴片电阻510R 1% 1/16W 0402
R51 = RES: CLASS: DISCRETE; 规格: 贴片电阻1M 1% 1/8W 0805; 规格编号: AC0805FR-071ML; 条码: EBF29070294; 品牌: 国巨; 类别: 贴片电阻0805; 规格书: YAGEO国巨厚膜无铅电阻.pdf; 价格: 0.02396; 生命周期: 量产
R130 R131 R136 R138 = RES: CLASS: DISCRETE; 生命周期: 量产; 价格: 0.002773; 规格书: 厚声-无铅厚膜电阻.pdf; 类别: 贴片电阻0402; 品牌: 厚声; 条码: EBF29070046; 规格编号: 0402WGF1002TCE; 规格: 贴片电阻10K 1% 1/16W 0402
R132 = RES: CLASS: DISCRETE; 生命周期: 量产; 规格书: 合科泰-RI系列电阻.pdf; 类别: 贴片电阻0603; 品牌: 合科泰; 条码: EBF29070063; 规格编号: RI0603L0000FT; 规格: 贴片电阻0R 1% 1/10W 0603
R133 = RES: CLASS: DISCRETE; 类别: 贴片电阻0603; 条码: EBF29070088; 规格: 贴片电阻NC 预留
R134 = RES: CLASS: DISCRETE; 生命周期: 量产; 价格: 0.0093; 规格书: 厚声-无铅厚膜电阻.pdf; 类别: 贴片电阻0805; 品牌: 厚声; 条码: EBF29070197; 规格编号: 0805W8F100JT5E; 规格: 贴片电阻10R 1% 1/8W 0805
R135 = RES: CLASS: DISCRETE; 生命周期: 量产; 规格书: 合科泰-RI系列电阻.pdf; 类别: 贴片电阻0402; 品牌: 合科泰; 条码: EBF29070181; 规格编号: RI0402L22R0FT; 规格: 贴片电阻22R 1% 1/16W 0402
R137 = RES: as R10 on sheet 03 电源
T1 T7 = IND-4P: 规格: 贴片共模电感  片式网络变压器专用 阻抗800欧姆 电流300mA; 条码: EBF29050062; 品牌: 德立; 类别: 贴片共模电感; 规格书: 德立_WBA0805D801PT-HF.pdf; 价格: 0.13262; 生命周期: 量产
T2 T4 T6 = IND-4P: 生命周期: 量产; 价格: 0.144102; 规格书: 德立_WBA3416L600T-D-HF.pdf; 类别: 贴片共模电感; 品牌: 德立; 条码: EBF29050063; 规格: 贴片共模电感  片式网络变压器专用 电感60uH 额定200mA电流
T3 T5 = IND-4P: 生命周期: 量产; 价格: 0.13262; 规格书: 德立_WBA0805D801PT-HF.pdf; 类别: 贴片共模电感; 品牌: 德立; 条码: EBF29050062; 规格: 贴片共模电感  片式网络变压器专用 阻抗800欧姆 电流300mA
T8 = IND-4P: 规格: 贴片共模电感  片式网络变压器专用 电感60uH 额定200mA电流; 条码: EBF29050063; 品牌: 德立; 类别: 贴片共模电感; 规格书: 德立_WBA3416L600T-D-HF.pdf; 价格: 0.144102; 生命周期: 量产
U15 = HYM8563S: 备注: 鲁班猫系列板子; 生命周期: 量产; 价格: 0.8789; 规格书: 捷茂微_BM8563EMA.pdf; 类别: 实时时钟芯片; 品牌: 捷茂微; 条码: EBFCIS240229100017; 规格: 工作电压1.5V~5.5V 日期格式YY-MM-DD 时间格式HH:MM:SS 接口类型I2C 电流消耗0.25uA~@3.0V
Y3 = CRYSTAL_2P: 生命周期: 量产; 价格: 2.57; 规格书: 爱普生-32.768KHz.pdf; 类别: 贴片晶振 3215; 品牌: 爱普生; 条码: EBF29100004; 规格编号: Q13FC1350000300; 规格: 无源晶振32.768KHz 70KΩ 9pF 3215

## Sheet 06 音频_SD卡.SchDoc
size 297 x 209 mm
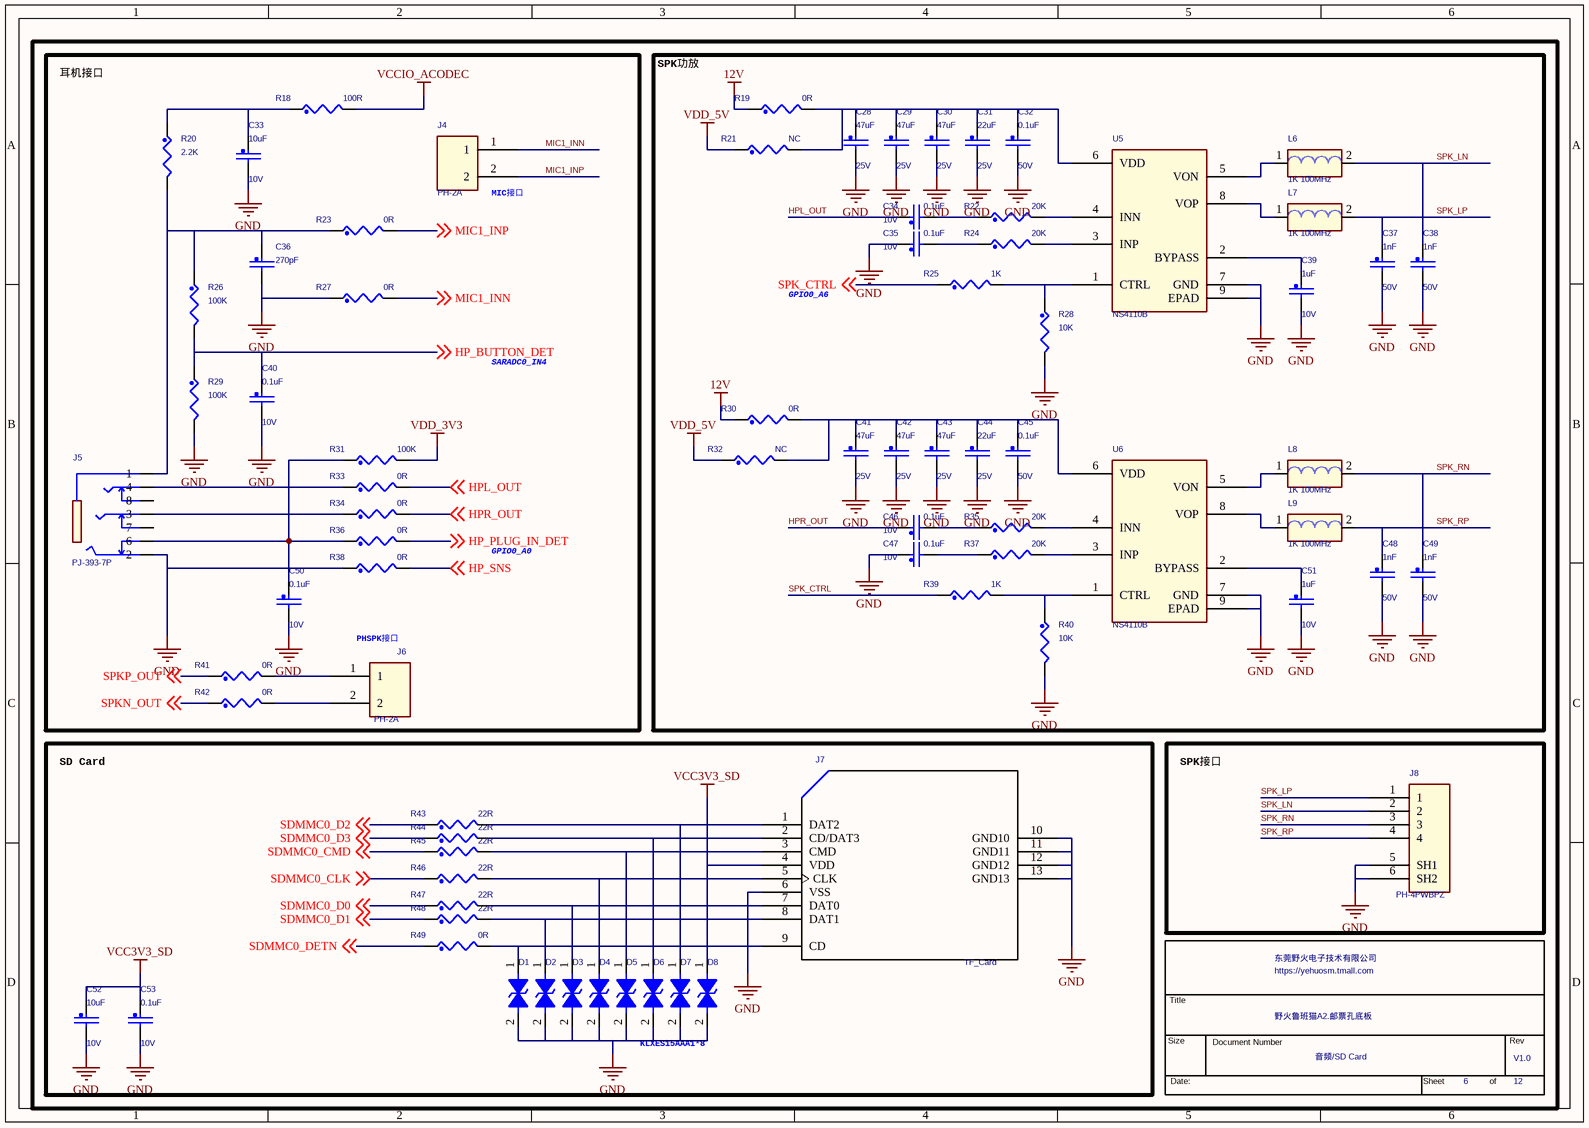
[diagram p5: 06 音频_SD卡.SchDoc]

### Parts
(Parts that share a designator on the sheet are numbered #1, #2 ... from top to bottom, then left to right.)
*#6  Page Count: 12  Page Number: 6  OrgName: 东莞野火电子技术有限公司  Title: 野火鲁班猫A2.邮票孔底板  RevCode: V1.0  Doc: 音频/SD Card  (hidden comment: TitleBlock_YHSCH)  (graphical)
C28  47uF  Voltage: 25V  [C1206]
C29  47uF  Voltage: 25V  [C1206]
C30  47uF  Voltage: 25V  [C1206]
C31  22uF  Voltage: 25V  [C0805]
C32  0.1uF  Voltage: 50V  [C0402]
C33  10uF  Voltage: 10V  [C0402]
C34  0.1uF  Voltage: 10V  [C0402]
C35  0.1uF  Voltage: 10V  [C0402]
C36  270pF  [C0402]
C37  1nF  Voltage: 50V  [C0402]
C38  1nF  Voltage: 50V  [C0402]
C39  1uF  Voltage: 10V  [C0402]
C40  0.1uF  Voltage: 10V  [C0402]
C41  47uF  Voltage: 25V  [C1206]
C42  47uF  Voltage: 25V  [C1206]
C43  47uF  Voltage: 25V  [C1206]
C44  22uF  Voltage: 25V  [C0805]
C45  0.1uF  Voltage: 50V  [C0402]
C46  0.1uF  Voltage: 10V  [C0402]
C47  0.1uF  Voltage: 10V  [C0402]
C48  1nF  Voltage: 50V  [C0402]
C49  1nF  Voltage: 50V  [C0402]
C50  0.1uF  Voltage: 10V  [C0402]
C51  1uF  Voltage: 10V  [C0402]
C52  10uF  Voltage: 10V  [C0402]
C53  0.1uF  Voltage: 10V  [C0402]
D1  KLXES15AAA1  [D0603/SMD]  (value not drawn)
D2  KLXES15AAA1  [D0603/SMD]  (value not drawn)
D3  KLXES15AAA1  [D0603/SMD]  (value not drawn)
D4  KLXES15AAA1  [D0603/SMD]  (value not drawn)
D5  KLXES15AAA1  [D0603/SMD]  (value not drawn)
D6  KLXES15AAA1  [D0603/SMD]  (value not drawn)
D7  KLXES15AAA1  [D0603/SMD]  (value not drawn)
D8  KLXES15AAA1  [D0603/SMD]  (value not drawn)
J4  PH-2A  [PH-1x2-2P0_l]
J5  PJ-393-7P  [audio_smd_7p_6r0x8r8]
J6  PH-2A  [PH-1x2-2P0_l]
J7  TF_Card  [TFCARD]
J8  PH-4PWBPZ  [ph2r0-a-1x4]
L6  1K 100MHz  [L0603]
L7  1K 100MHz  [L0603]
L8  1K 100MHz  [L0603]
L9  1K 100MHz  [L0603]
R18  100R  [R0402]
R19  0R  [R0603]
R20  2.2K  [R0402]
R21  NC  [R0603]
R22  20K  [R0402]
R23  0R  [R0402]
R24  20K  [R0402]
R25  1K  [R0402]
R26  100K  [R0402]
R27  0R  [R0402]
R28  10K  [R0402]
R29  100K  [R0402]
R30  0R  [R0603]
R31  100K  [R0402]
R32  NC  [R0603]
R33  0R  [R0402]
R34  0R  [R0402]
R35  20K  [R0402]
R36  0R  [R0402]
R37  20K  [R0402]
R38  0R  [R0402]
R39  1K  [R0402]
R40  10K  [R0402]
R41  0R  [R0402]
R42  0R  [R0402]
R43  22R  [R0402]
R44  22R  [R0402]
R45  22R  [R0402]
R46  22R  [R0402]
R47  22R  [R0402]
R48  22R  [R0402]
R49  0R  [R0402]
U5  NS4110B  [SOP-8-EP-2R5X3R4]
U6  NS4110B  [SOP-8-EP-2R5X3R4]

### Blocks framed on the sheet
耳机接口: C33 C36 C40 C50 J4-J6 R18 R20 R23 R26 R27 R29 R31 R33 R34 R36 R38 R41 R42
SPK功放: C28-C32 C34 C35 C37-C39 C41-C49 C51 L6-L9 R19 R21 R22 R24 R25 R28 R30 R32 R35 R37 R39 R40 U5 U6
SD Card: C52 C53 D1-D8 J7 R43-R49
SPK接口: J8

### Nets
12V: R19.1 R30.1
GND: C28.2 C29.2 C30.2 C31.2 C32.2 C33.2 C35.1 C36.2 C37.2 C38.2 C39.2 C40.2 C41.2 C42.2 C43.2 C44.2 C45.2 C47.1 C48.2 C49.2 C50.2 C51.2 C52.2 C53.2 D1.2 D2.2 D3.2 D4.2 D5.2 D6.2 D7.2 D8.2 J5.2 J7.6(VSS) J7.10(GND10) J7.11(GND11) J7.12(GND12) J7.13(GND13) J8.5(SH1) J8.6(SH2) R27.1 R28.2 R29.2 R38.1 R40.2 U5.7(GND) U5.9(EPAD) U6.7(GND) U6.9(EPAD)
VCC3V3_SD: C52.1 C53.1 D8.1 J7.4(VDD)
VCCIO_ACODEC: R18.2
VDD_3V3: R31.2
VDD_5V: R21.1 R32.1
HP_BUTTON_DET: C40.1 R26.2 R29.1 ; off-sheet HP_BUTTON_DET
HP_PLUG_IN_DET: R36.2 ; off-sheet HP_PLUG_IN_DET
HP_SNS: R38.2 ; off-sheet HP_SNS
HPL_OUT: C34.1 R33.2 ; off-sheet HPL_OUT
HPR_OUT: C46.1 R34.2 ; off-sheet HPR_OUT
MIC1_INN: J4.1 R27.2 ; off-sheet MIC1_INN
MIC1_INP: J4.2 R23.2 ; off-sheet MIC1_INP
SDMMC0_CLK: R46.1 ; off-sheet SDMMC0_CLK
SDMMC0_CMD: R45.1 ; off-sheet SDMMC0_CMD
SDMMC0_D0: R47.1 ; off-sheet SDMMC0_D0
SDMMC0_D1: R48.1 ; off-sheet SDMMC0_D1
SDMMC0_D2: R43.1 ; off-sheet SDMMC0_D2
SDMMC0_D3: R44.1 ; off-sheet SDMMC0_D3
SDMMC0_DETN: R49.1 ; off-sheet SDMMC0_DETN
SPK_CTRL: R25.1 R39.1 ; off-sheet SPK_CTRL
SPK_LN: C38.1 J8.2 L6.2
SPK_LP: C37.1 J8.1 L7.2
SPK_RN: C49.1 J8.3 L8.2
SPK_RP: C48.1 J8.4 L9.2
SPKN_OUT: R42.1 ; off-sheet SPKN_OUT
SPKP_OUT: R41.1 ; off-sheet SPKP_OUT
NetC28_1: C28.1 C29.1 C30.1 C31.1 C32.1 R19.2 R21.2 U5.6(VDD)
NetC33_1: C33.1 R18.1 R20.1
NetC34_2: C34.2 R22.1
NetC35_2: C35.2 R24.1
NetC36_1: C36.1 J5.1 R20.2 R23.1 R26.1
NetC39_1: C39.1 U5.2(BYPASS)
NetC41_1: C41.1 C42.1 C43.1 C44.1 C45.1 R30.2 R32.2 U6.6(VDD)
NetC46_2: C46.2 R35.1
NetC47_2: C47.2 R37.1
NetC50_1: C50.1 J5.6 R31.1 R36.1
NetC51_1: C51.1 U6.2(BYPASS)
NetD1_1: D1.1 J7.9(CD) R49.2
NetD2_1: D2.1 J7.8(DAT1) R48.2
NetD3_1: D3.1 J7.7(DAT0) R47.2
NetD4_1: D4.1 J7.5(CLK) R46.2
NetD5_1: D5.1 J7.3(CMD) R45.2
NetD6_1: D6.1 J7.2(CD/DAT3) R44.2
NetD7_1: D7.1 J7.1(DAT2) R43.2
NetJ5_3: J5.3 R34.1
NetJ5_4: J5.4 R33.1
NetJ6_1: J6.1 R41.2
NetJ6_2: J6.2 R42.2
NetL6_1: L6.1 U5.5(VON)
NetL7_1: L7.1 U5.8(VOP)
NetL8_1: L8.1 U6.5(VON)
NetL9_1: L9.1 U6.8(VOP)
NetR22_2: R22.2 U5.4(INN)
NetR24_2: R24.2 U5.3(INP)
NetR25_2: R25.2 R28.1 U5.1(CTRL)
NetR35_2: R35.2 U6.4(INN)
NetR37_2: R37.2 U6.3(INP)
NetR39_2: R39.2 R40.1 U6.1(CTRL)

Not connected (* = marked no-connect by the designer): J5 7 8

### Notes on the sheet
- (near J4) MIC接口
- GPIO0_A6
- SARADC0_IN4
- GPIO0_A0
- (near J6) PHSPK接口
- KLXES15AAA1*8

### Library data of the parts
*#6 = TitleBlock_YHSCH: Cage Code: 1
C28-C30 = CAP_NP: CLASS: DISCRETE; 生命周期: 量产; 价格: 1.12; 规格书: 村田贴片电容.pdf; 类别: 贴片电容1206; 品牌: 村田; 条码: EBF29060192; 规格编号: GRM31CR61E476ME44L; 规格: 贴片电容47uF 20% 25V X5R 1206
C31 C44 = CAP_NP: as C5 on sheet 03 电源
C32 = CAP_NP: as C6 on sheet 03 电源
C33 C52 = CAP_NP: as C116 on sheet 05 RJ45网口_RTC_FAN
C34 C35 C40 C46 C47 C50 = CAP_NP: as C1 on sheet 03 电源
C36 = CAP_NP: Voltage: 50V; CLASS: DISCRETE; 生命周期: 量产; 价格: 0.018204; 规格书: 风华电容.pdf; 类别: 贴片电容0402; 品牌: 风华; 条码: EBF29060290; 规格编号: 0402CG271J500NT; 规格: 贴片电容270pF 5% 50V C0G 0402
C37 C38 = CAP_NP: CLASS: DISCRETE; 生命周期: 量产; 价格: 0.006195; 规格书: 风华电容.pdf; 类别: 贴片电容0402; 品牌: 风华; 条码: EBF29060175; 规格编号: 0402B102M500NT; 规格: 贴片电容1nF 20% 50V X7R 0402
C39 = CAP_NP: CLASS: DISCRETE; 生命周期: 量产; 价格: 0.01191; 规格书: 风华电容.pdf; 类别: 贴片电容0402; 品牌: 风华; 条码: EBF29060121; 规格编号: 0402X105K100NT; 规格: 贴片电容1uF 10% 10V X5R 0402
C41-C43 = CAP_NP: CLASS: DISCRETE; 规格: 贴片电容47uF 20% 25V X5R 1206; 规格编号: GRM31CR61E476ME44L; 条码: EBF29060192; 品牌: 村田; 类别: 贴片电容1206; 规格书: 村田贴片电容.pdf; 价格: 1.12; 生命周期: 量产
C45 = CAP_NP: as C19 on sheet 03 电源
C48 C49 = CAP_NP: CLASS: DISCRETE; 规格: 贴片电容1nF 20% 50V X7R 0402; 规格编号: 0402B102M500NT; 条码: EBF29060175; 品牌: 风华; 类别: 贴片电容0402; 规格书: 风华电容.pdf; 价格: 0.006195; 生命周期: 量产
C51 = CAP_NP: CLASS: DISCRETE; 规格: 贴片电容1uF 10% 10V X5R 0402; 规格编号: 0402X105K100NT; 条码: EBF29060121; 品牌: 风华; 类别: 贴片电容0402; 规格书: 风华电容.pdf; 价格: 0.01191; 生命周期: 量产
C53 = CAP_NP: as C54 on sheet 05 RJ45网口_RTC_FAN
D1-D8 = DIODE BI-DIR TRIG: 规格: 用于 USB3.0、HDMI 0.5pF、5V、±15kV ESD 保护二极管; 条码: EBF29140063; 品牌: 永裕泰; 类别: 贴片ESD; 规格书: KLXES15AAA1.pdf; 价格: 0.09719; 生命周期: 量产
J4 J6 = 1X2PIN: 规格: 直针PH2.0-2P 间距2.0MM 拔插式 接插件; 条码: EBF29040005; 品牌: 博穆精密; 类别: PH连接器; 规格书: 博穆精密_PH2.0-A.pdf; 价格: 0.019031; 生命周期: 量产
J5 = PJ-393: 规格: PJ-393-7P_3.5MM四段式耳机插座 7pin 直插; 条码: EBFCIS230522094626; 类别: 耳机座; 规格书: 成旭辉_PJ-393-7P直插耳机座.pdf; 生命周期: 量产; 品牌: 成旭辉; 备注: RK3566广告机
J7 = TF_Card: CLASS: IO; 可替代料: EBF29040003; 生命周期: 量产; 价格: 0.48; 规格书: 硕方-TF-015.pdf; 类别: SD卡连接器; 品牌: 硕方; 规格编号: TF-015; 规格: MICRO SD 卡座 TF T-Flash 外焊 双压片 自弹贴片
J8 = 1X4PIN_SH: 生命周期: 量产; 价格: 0.23158; 规格书: 博穆精密_PH2.0-A.pdf; 类别: PH连接器; 品牌: 博穆精密; 条码: EBF29040117; 规格: 间距：2mm 插针结构：1x4P 排数：1 每排PIN数：4 公母：公型插针 安装方式：卧贴 额定电流：2A 工作温度范围：-25℃~+85℃
L6 L7 = BEAD: CLASS: DISCRETE; 备注: RK3566广告机; 生命周期: 量产; 价格: 0.149038; 规格书: 村田_BLM18H_SN系列磁珠.pdf; 类别: 贴片磁珠0603; 品牌: 村田; 条码: EBFCIS230428095012; 规格编号: BLM18HE102SN1D; 规格: 磁珠1K@100MHz额定电流600mA直流电阻350mΩ
L8 L9 = BEAD: CLASS: DISCRETE; 备注: RK3566广告机; 规格: 磁珠1K@100MHz额定电流600mA直流电阻350mΩ; 规格编号: BLM18HE102SN1D; 条码: EBFCIS230428095012; 品牌: 村田; 类别: 贴片磁珠0603; 规格书: 村田_BLM18H_SN系列磁珠.pdf; 价格: 0.149038; 生命周期: 量产
R18 = RES: CLASS: DISCRETE; 生命周期: 量产; 规格书: 合科泰-RI系列电阻.pdf; 类别: 贴片电阻0402; 品牌: 合科泰; 条码: EBF29070053; 规格编号: RI0402L1000FT; 规格: 贴片电阻100R 1% 1/16W 0402
R19 R30 = RES: CLASS: DISCRETE; 规格: 贴片电阻0R 1% 1/10W 0603; 规格编号: RI0603L0000FT; 条码: EBF29070063; 品牌: 合科泰; 类别: 贴片电阻0603; 规格书: 合科泰-RI系列电阻.pdf; 生命周期: 量产
R20 = RES: as R174 on sheet 04 邮票孔连接器
R21 R32 = RES: CLASS: DISCRETE; 规格: 贴片电阻NC 预留; 条码: EBF29070088; 类别: 贴片电阻0603
R22 R24 = RES: as R4 on sheet 03 电源
R23 R27 R33 R34 R41 = RES: CLASS: DISCRETE; 生命周期: 量产; 规格书: 合科泰-RI系列电阻.pdf; 类别: 贴片电阻0402; 品牌: 合科泰; 条码: EBF29070049; 规格编号: RI0402L000FT; 规格: 贴片电阻0R 1% 1/16W 0402
R25 = RES: as R10 on sheet 03 电源
R26 = RES: CLASS: DISCRETE; 生命周期: 量产; 规格书: 合科泰-RI系列电阻.pdf; 类别: 贴片电阻0402; 品牌: 合科泰; 条码: EBF29070054; 规格编号: RI0402L1003FT; 规格: 贴片电阻100K 1% 1/16W 0402
R28 = RES: as R2 on sheet 03 电源
R29 R31 = RES: as R14 on sheet 03 电源
R35 R37 = RES: as R9 on sheet 03 电源
R36 R38 R42 R49 = RES: CLASS: DISCRETE; 规格: 贴片电阻0R 1% 1/16W 0402; 规格编号: RI0402L000FT; 条码: EBF29070049; 品牌: 合科泰; 类别: 贴片电阻0402; 规格书: 合科泰-RI系列电阻.pdf; 生命周期: 量产
R39 = RES: as R3 on sheet 03 电源
R40 = RES: as R130 on sheet 05 RJ45网口_RTC_FAN
R43-R48 = RES: as R135 on sheet 05 RJ45网口_RTC_FAN
U5 U6 = NS4110B: 备注: RK3566广告机; 生命周期: 量产; 规格书: 纳芯威_NS4110B音频功放.pdf; 类别: 音频芯片; 品牌: 纳芯威; 条码: EBFCIS230518164803; 规格: 单声道AB/D类音频功率放大器 工作电压:6V~14V 输出功率:18W@4Ω 超低EMI 支持差分输入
